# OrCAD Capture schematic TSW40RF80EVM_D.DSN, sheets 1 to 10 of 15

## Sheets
1 SHEET 01 - COVER: title: COVER; rev: D; note: TSW40RF80EVM
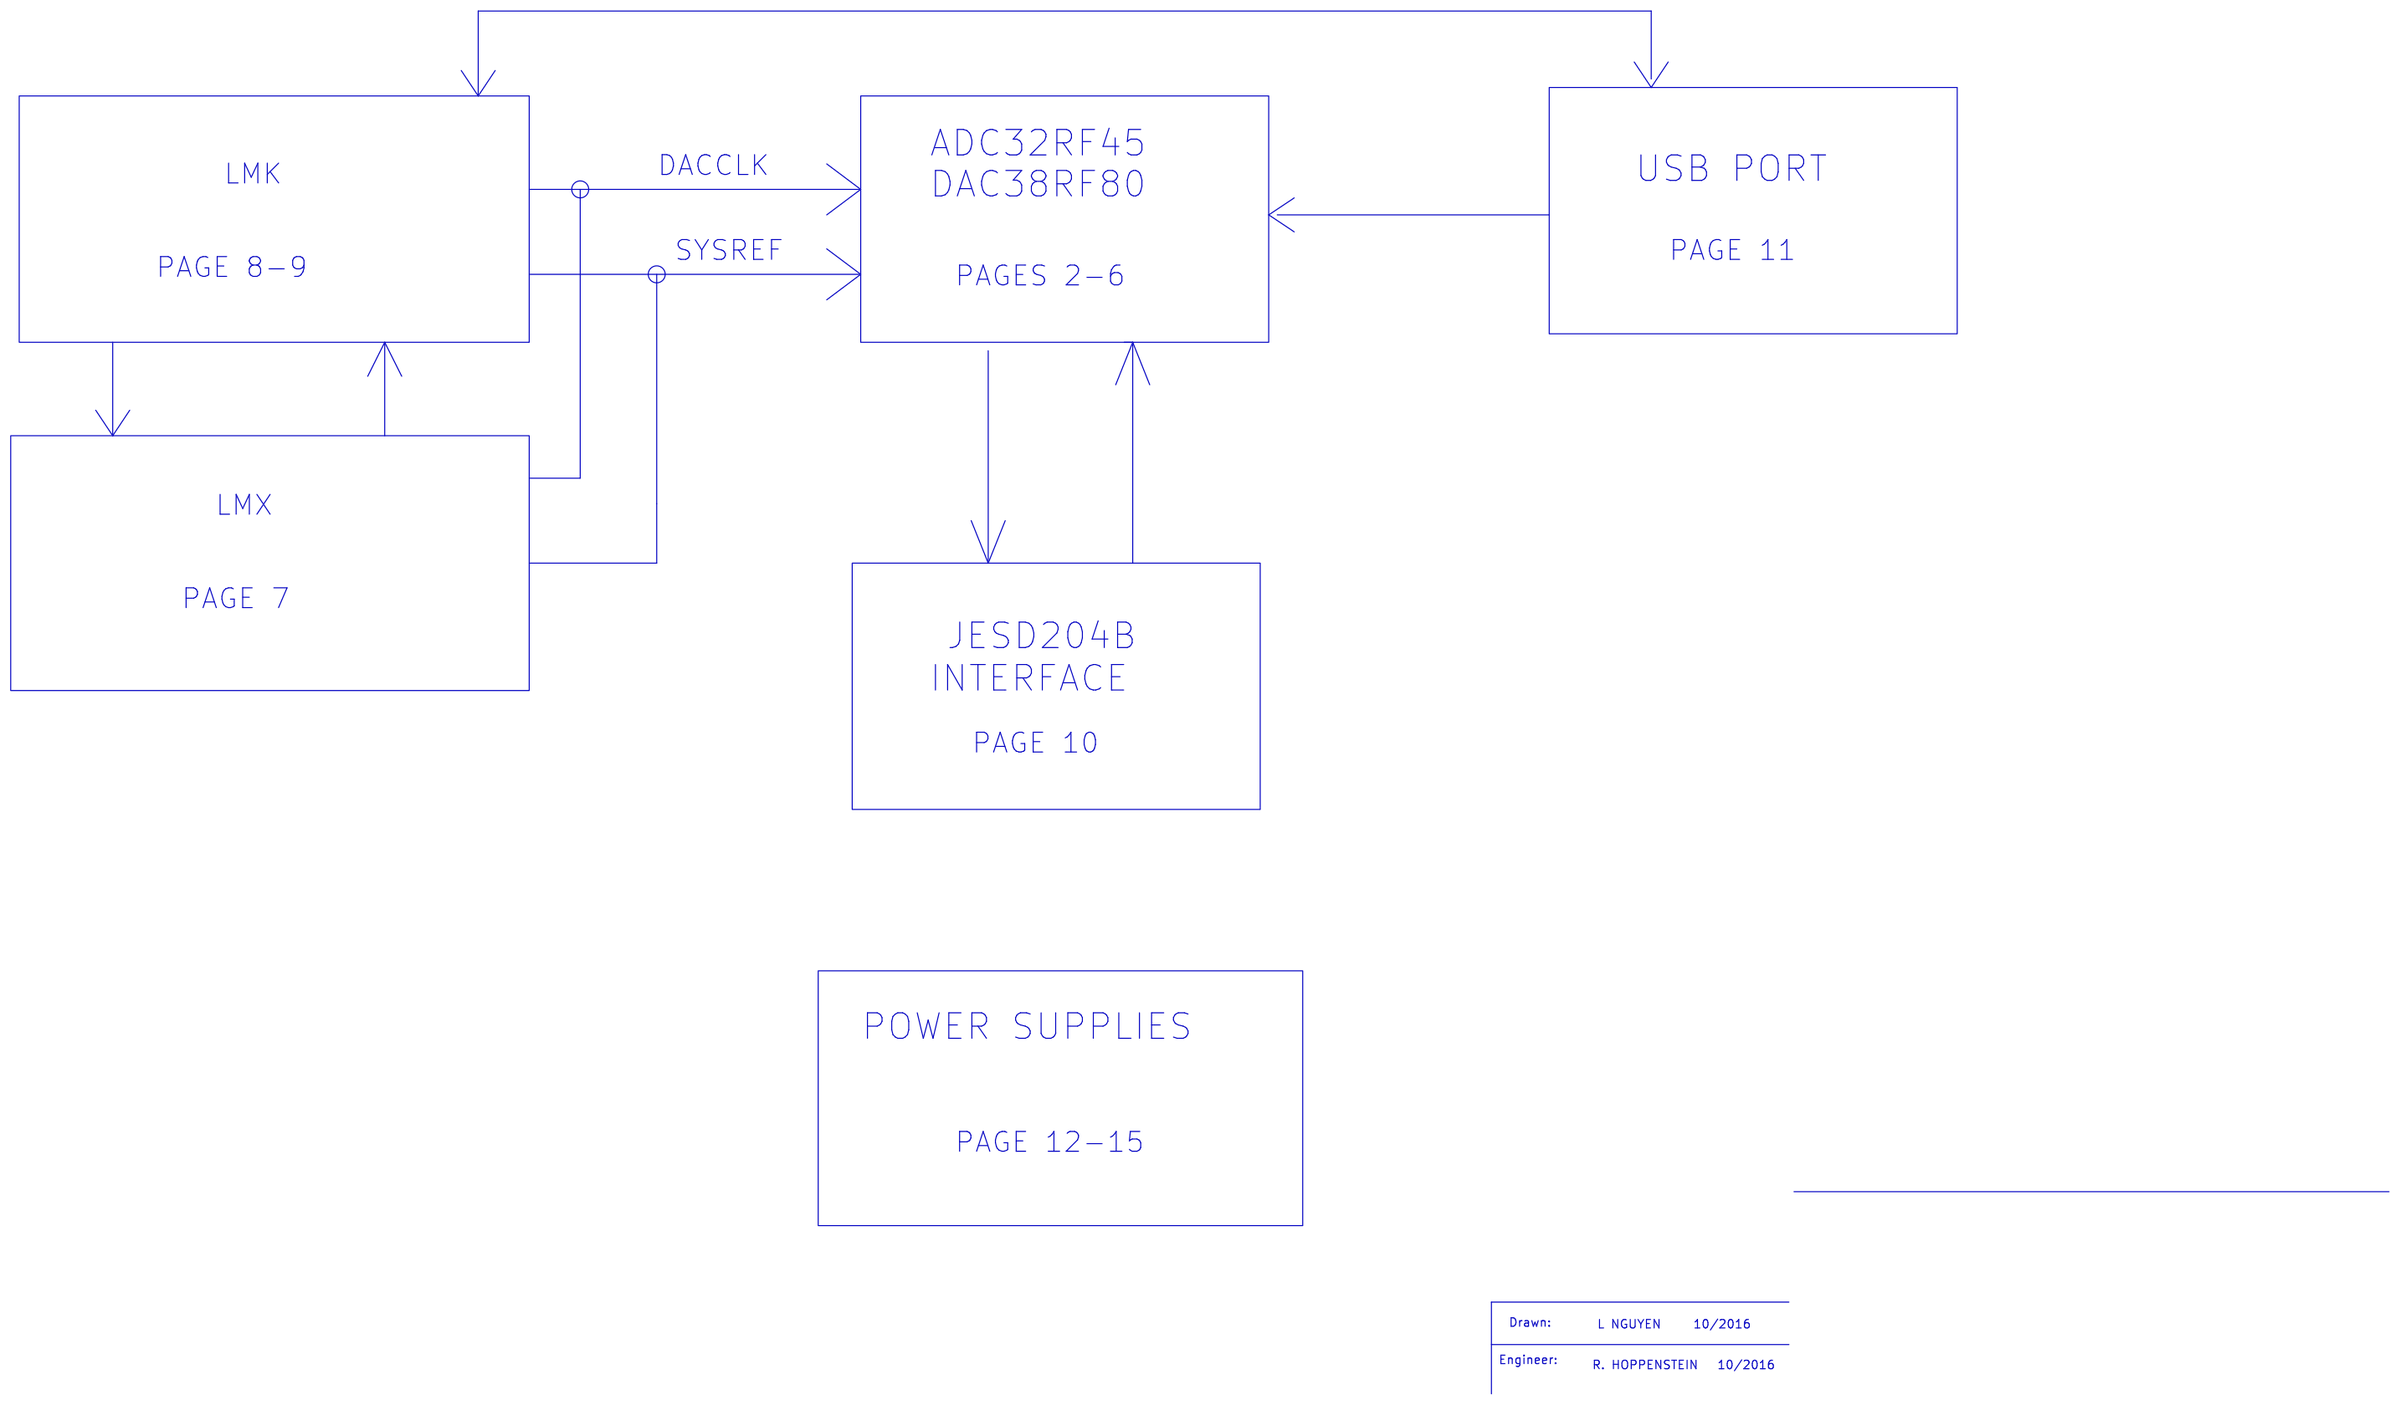
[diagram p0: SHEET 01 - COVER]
2 SHEET 02 - DAC: size B; title: DAC
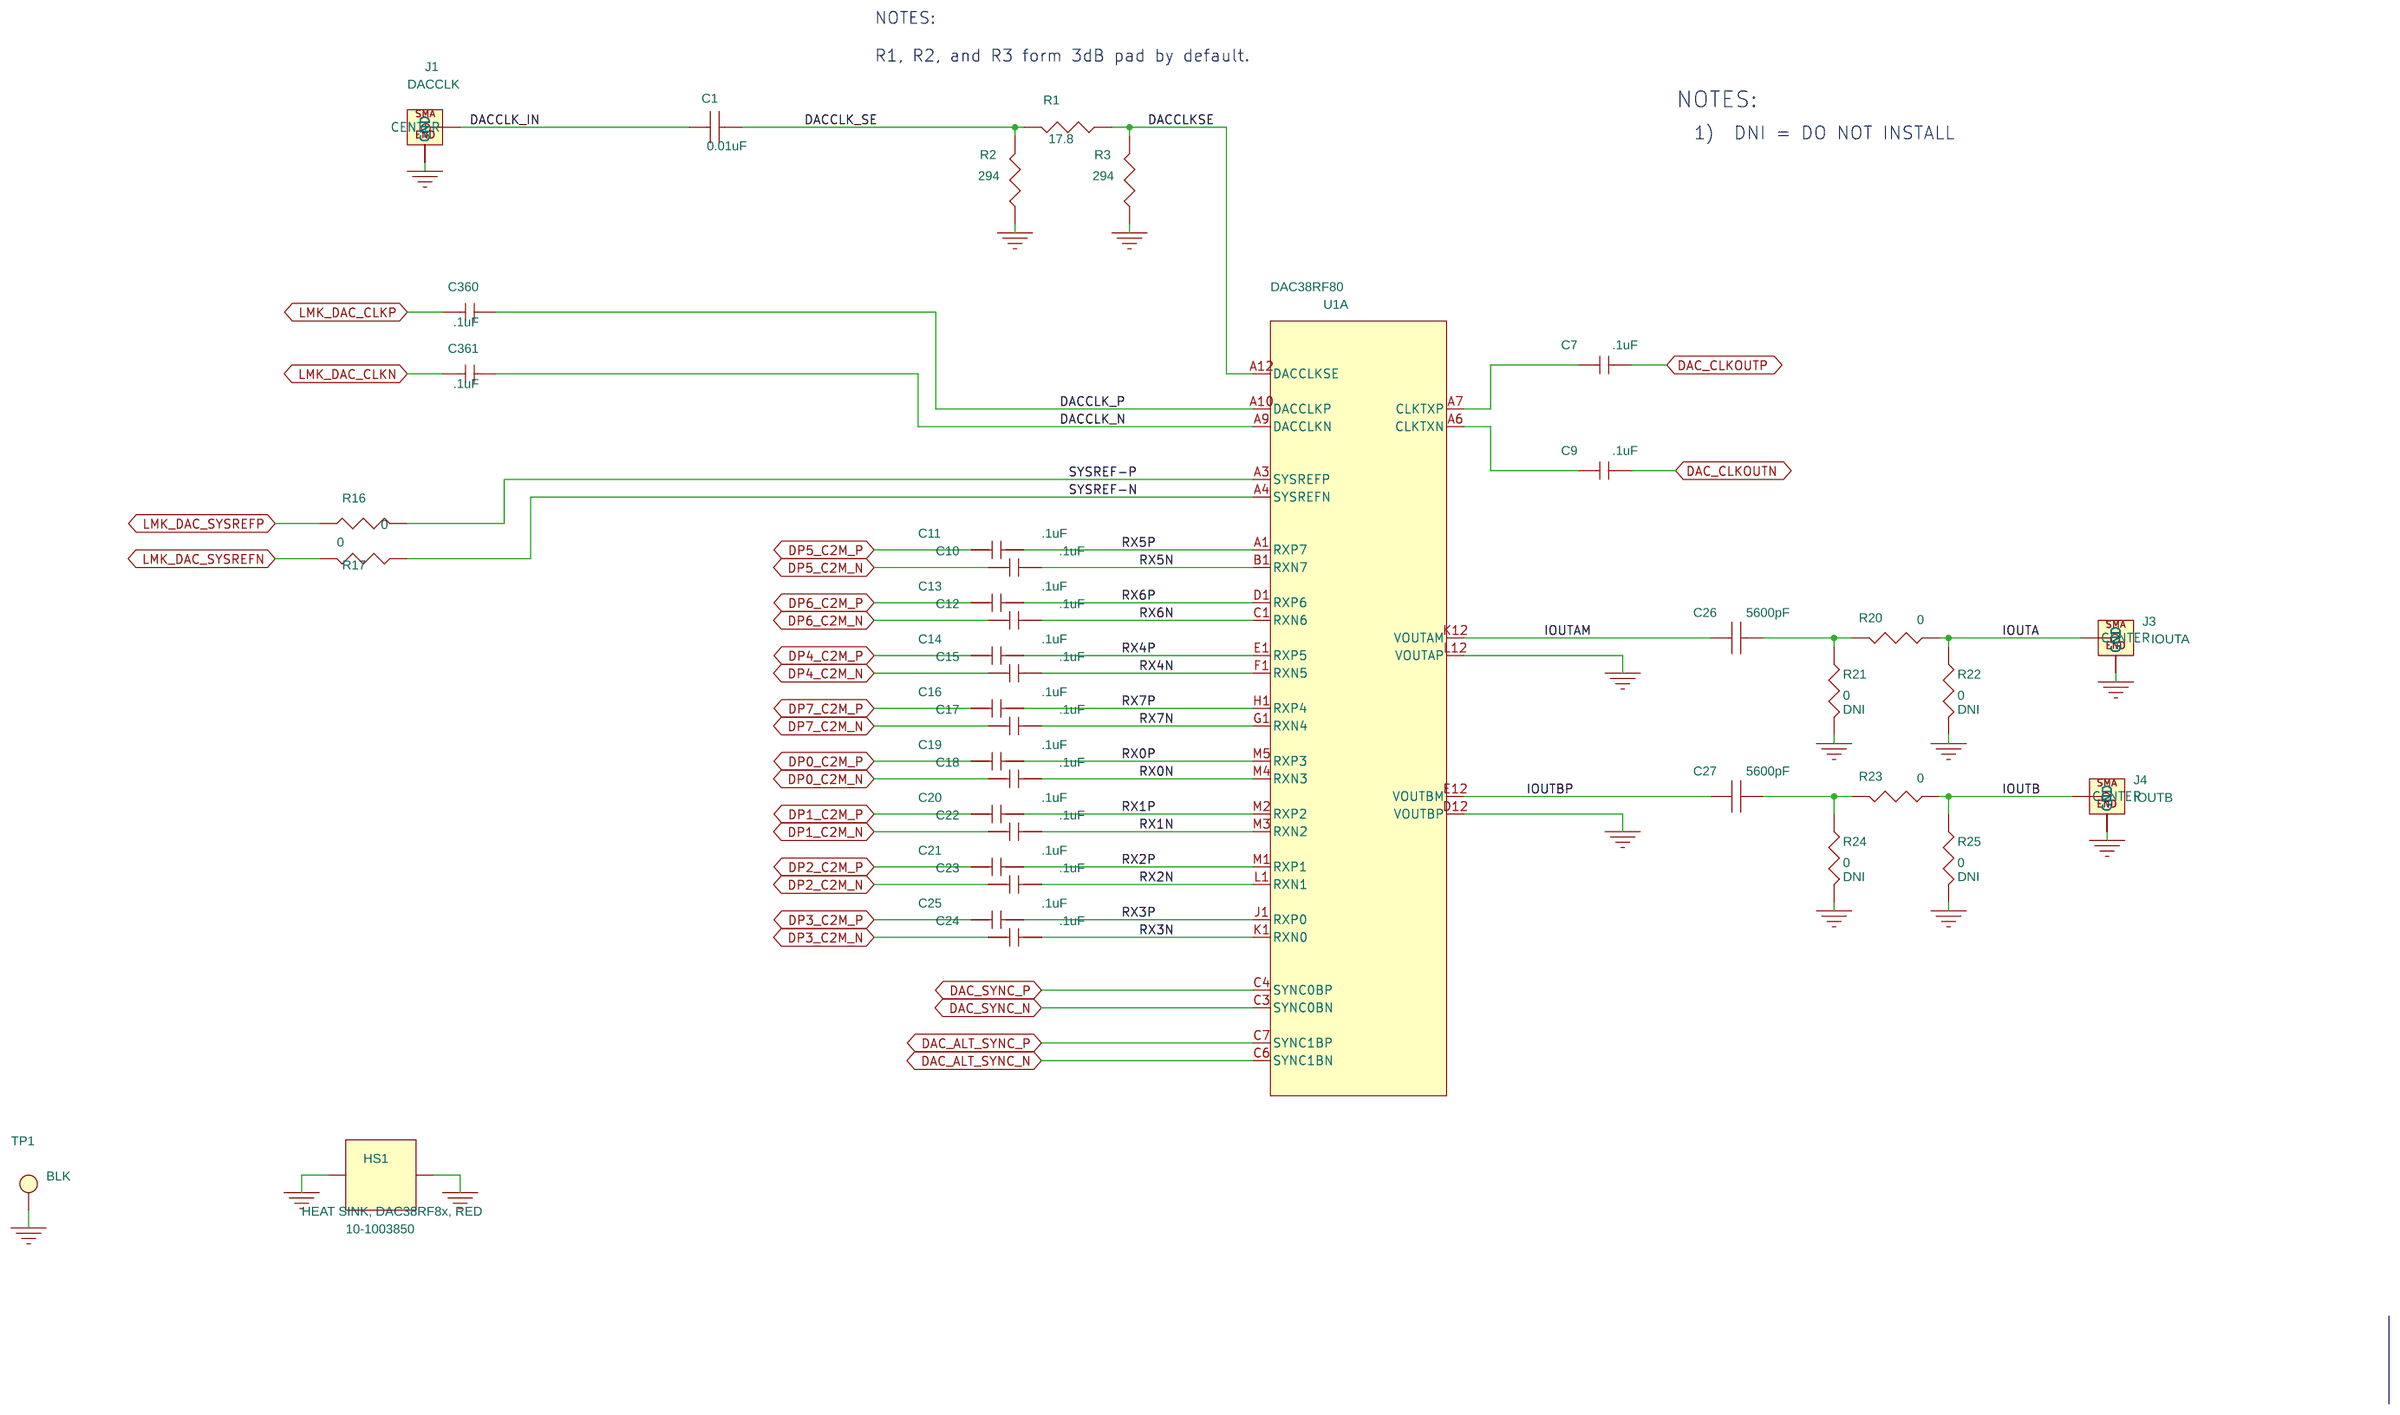
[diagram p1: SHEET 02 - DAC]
3 SHEET 03 - DAC OUTPUT: size B; title: DAC
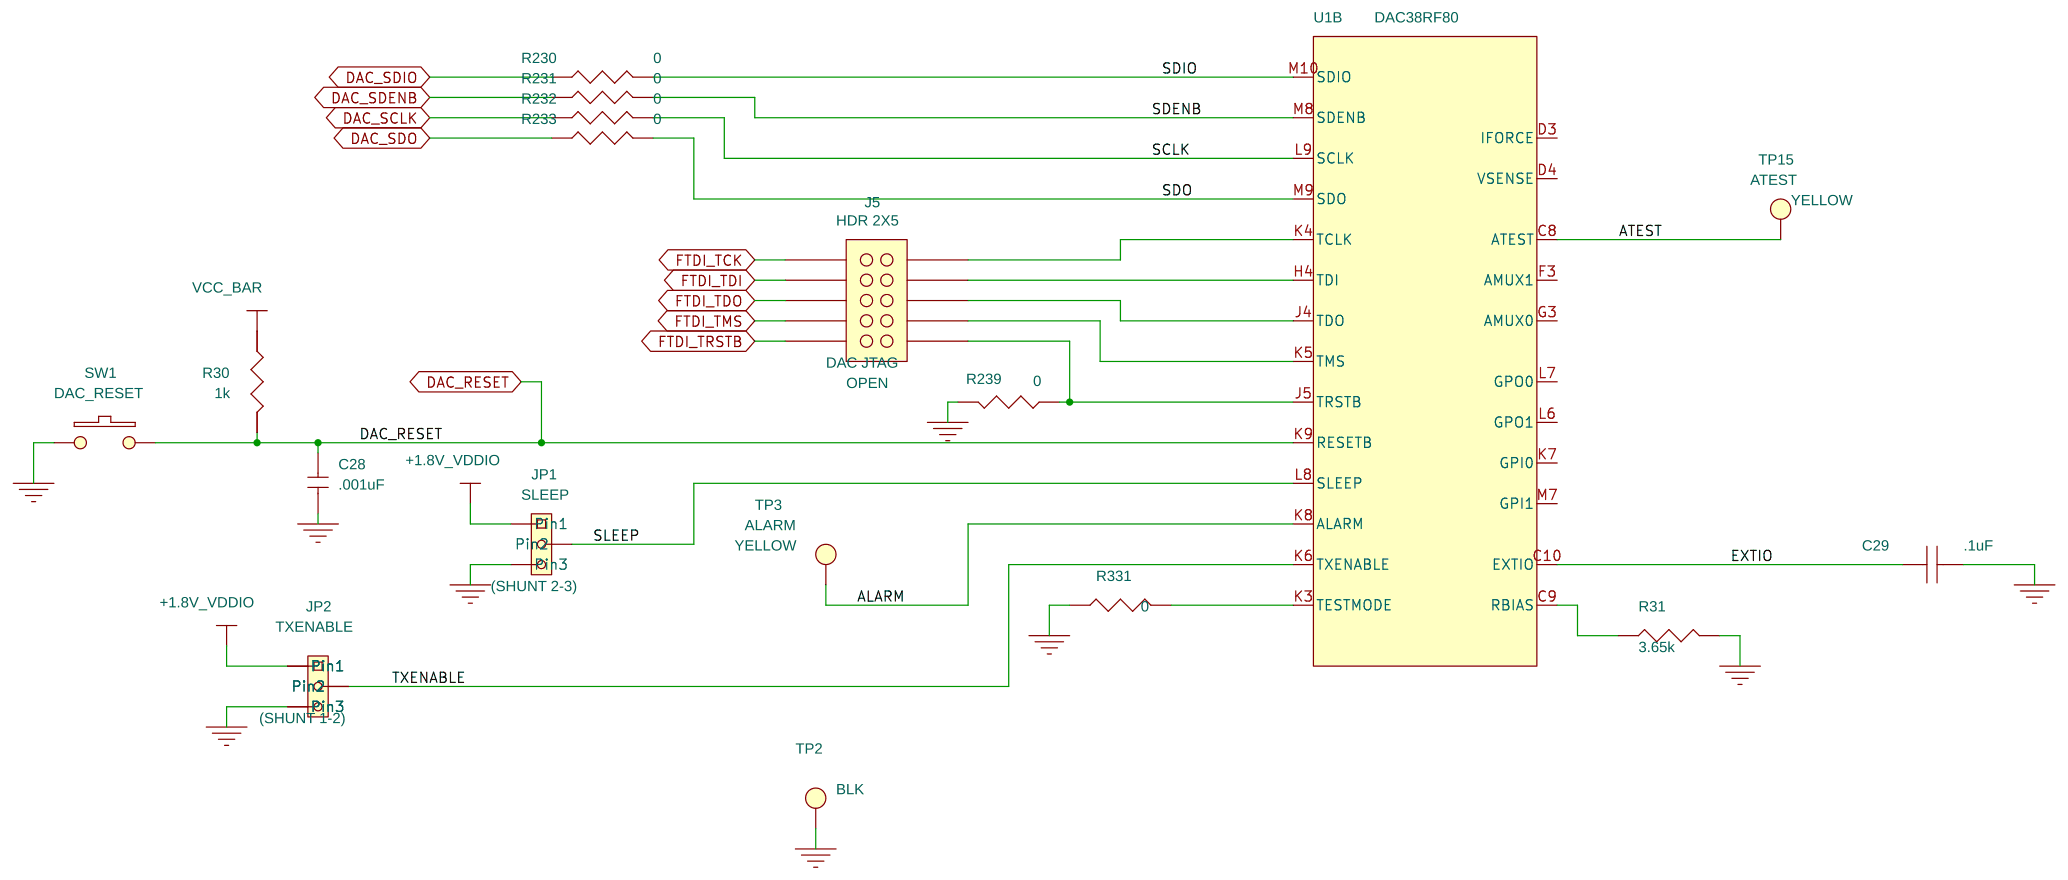
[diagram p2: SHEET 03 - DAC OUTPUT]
4 SHEET 04 - DAC POWER: size B; title: DAC POWER
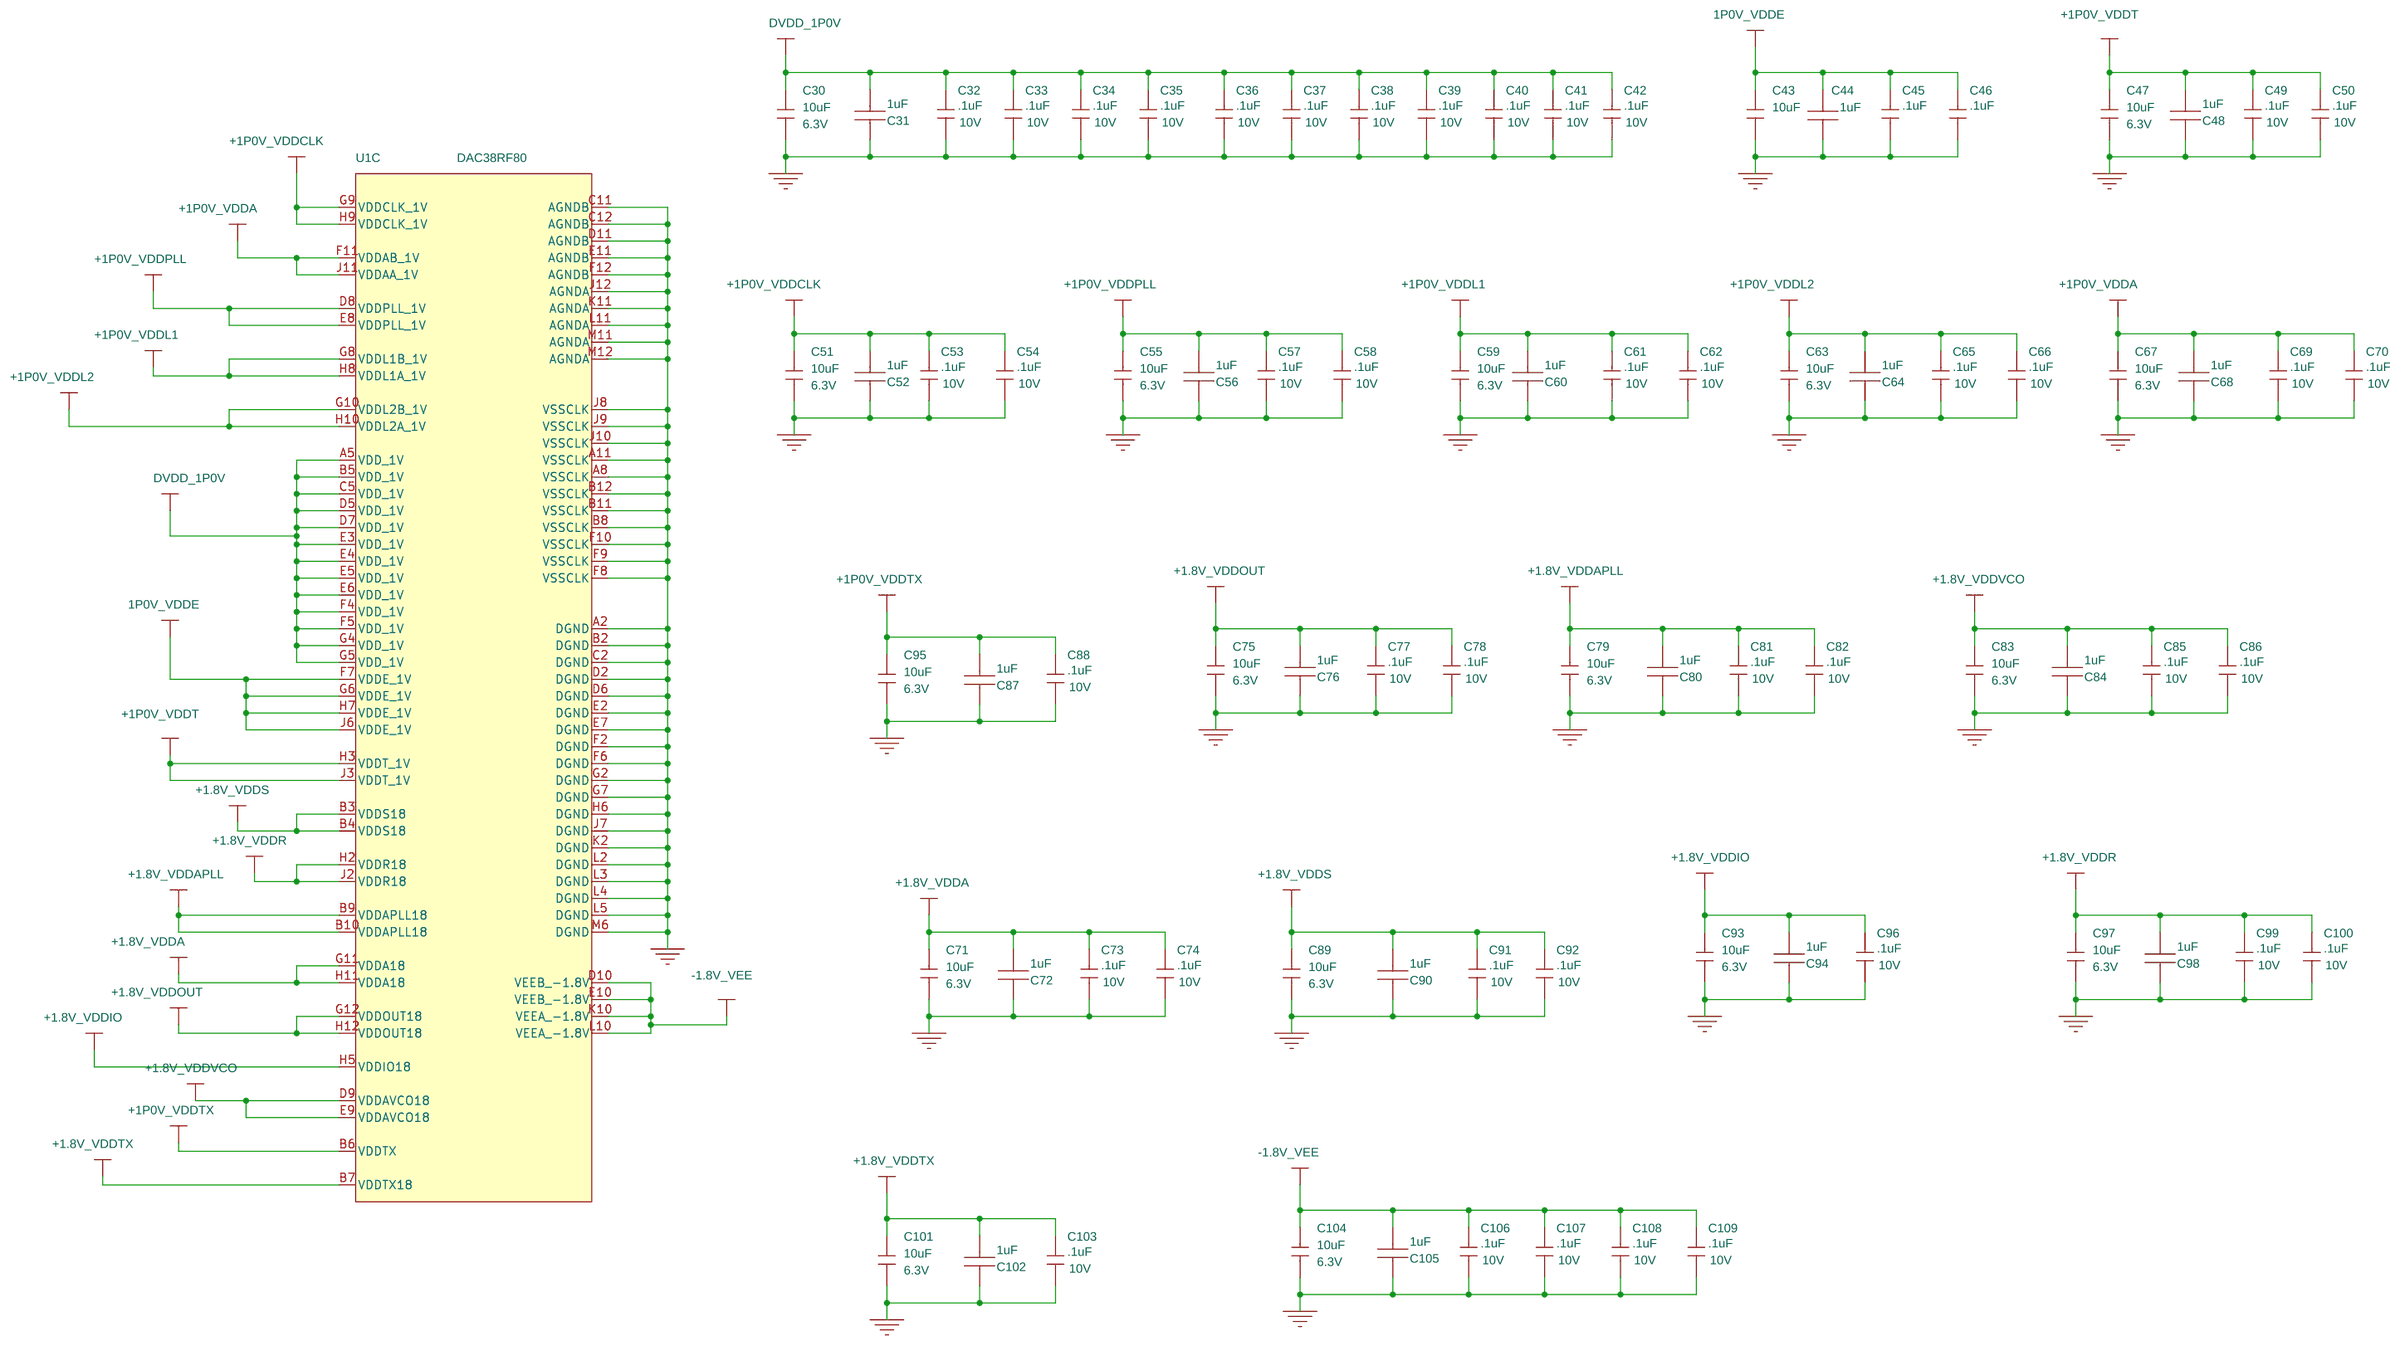
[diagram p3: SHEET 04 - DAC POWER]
5 SHEET 05 - ADC: size B; title: ADC
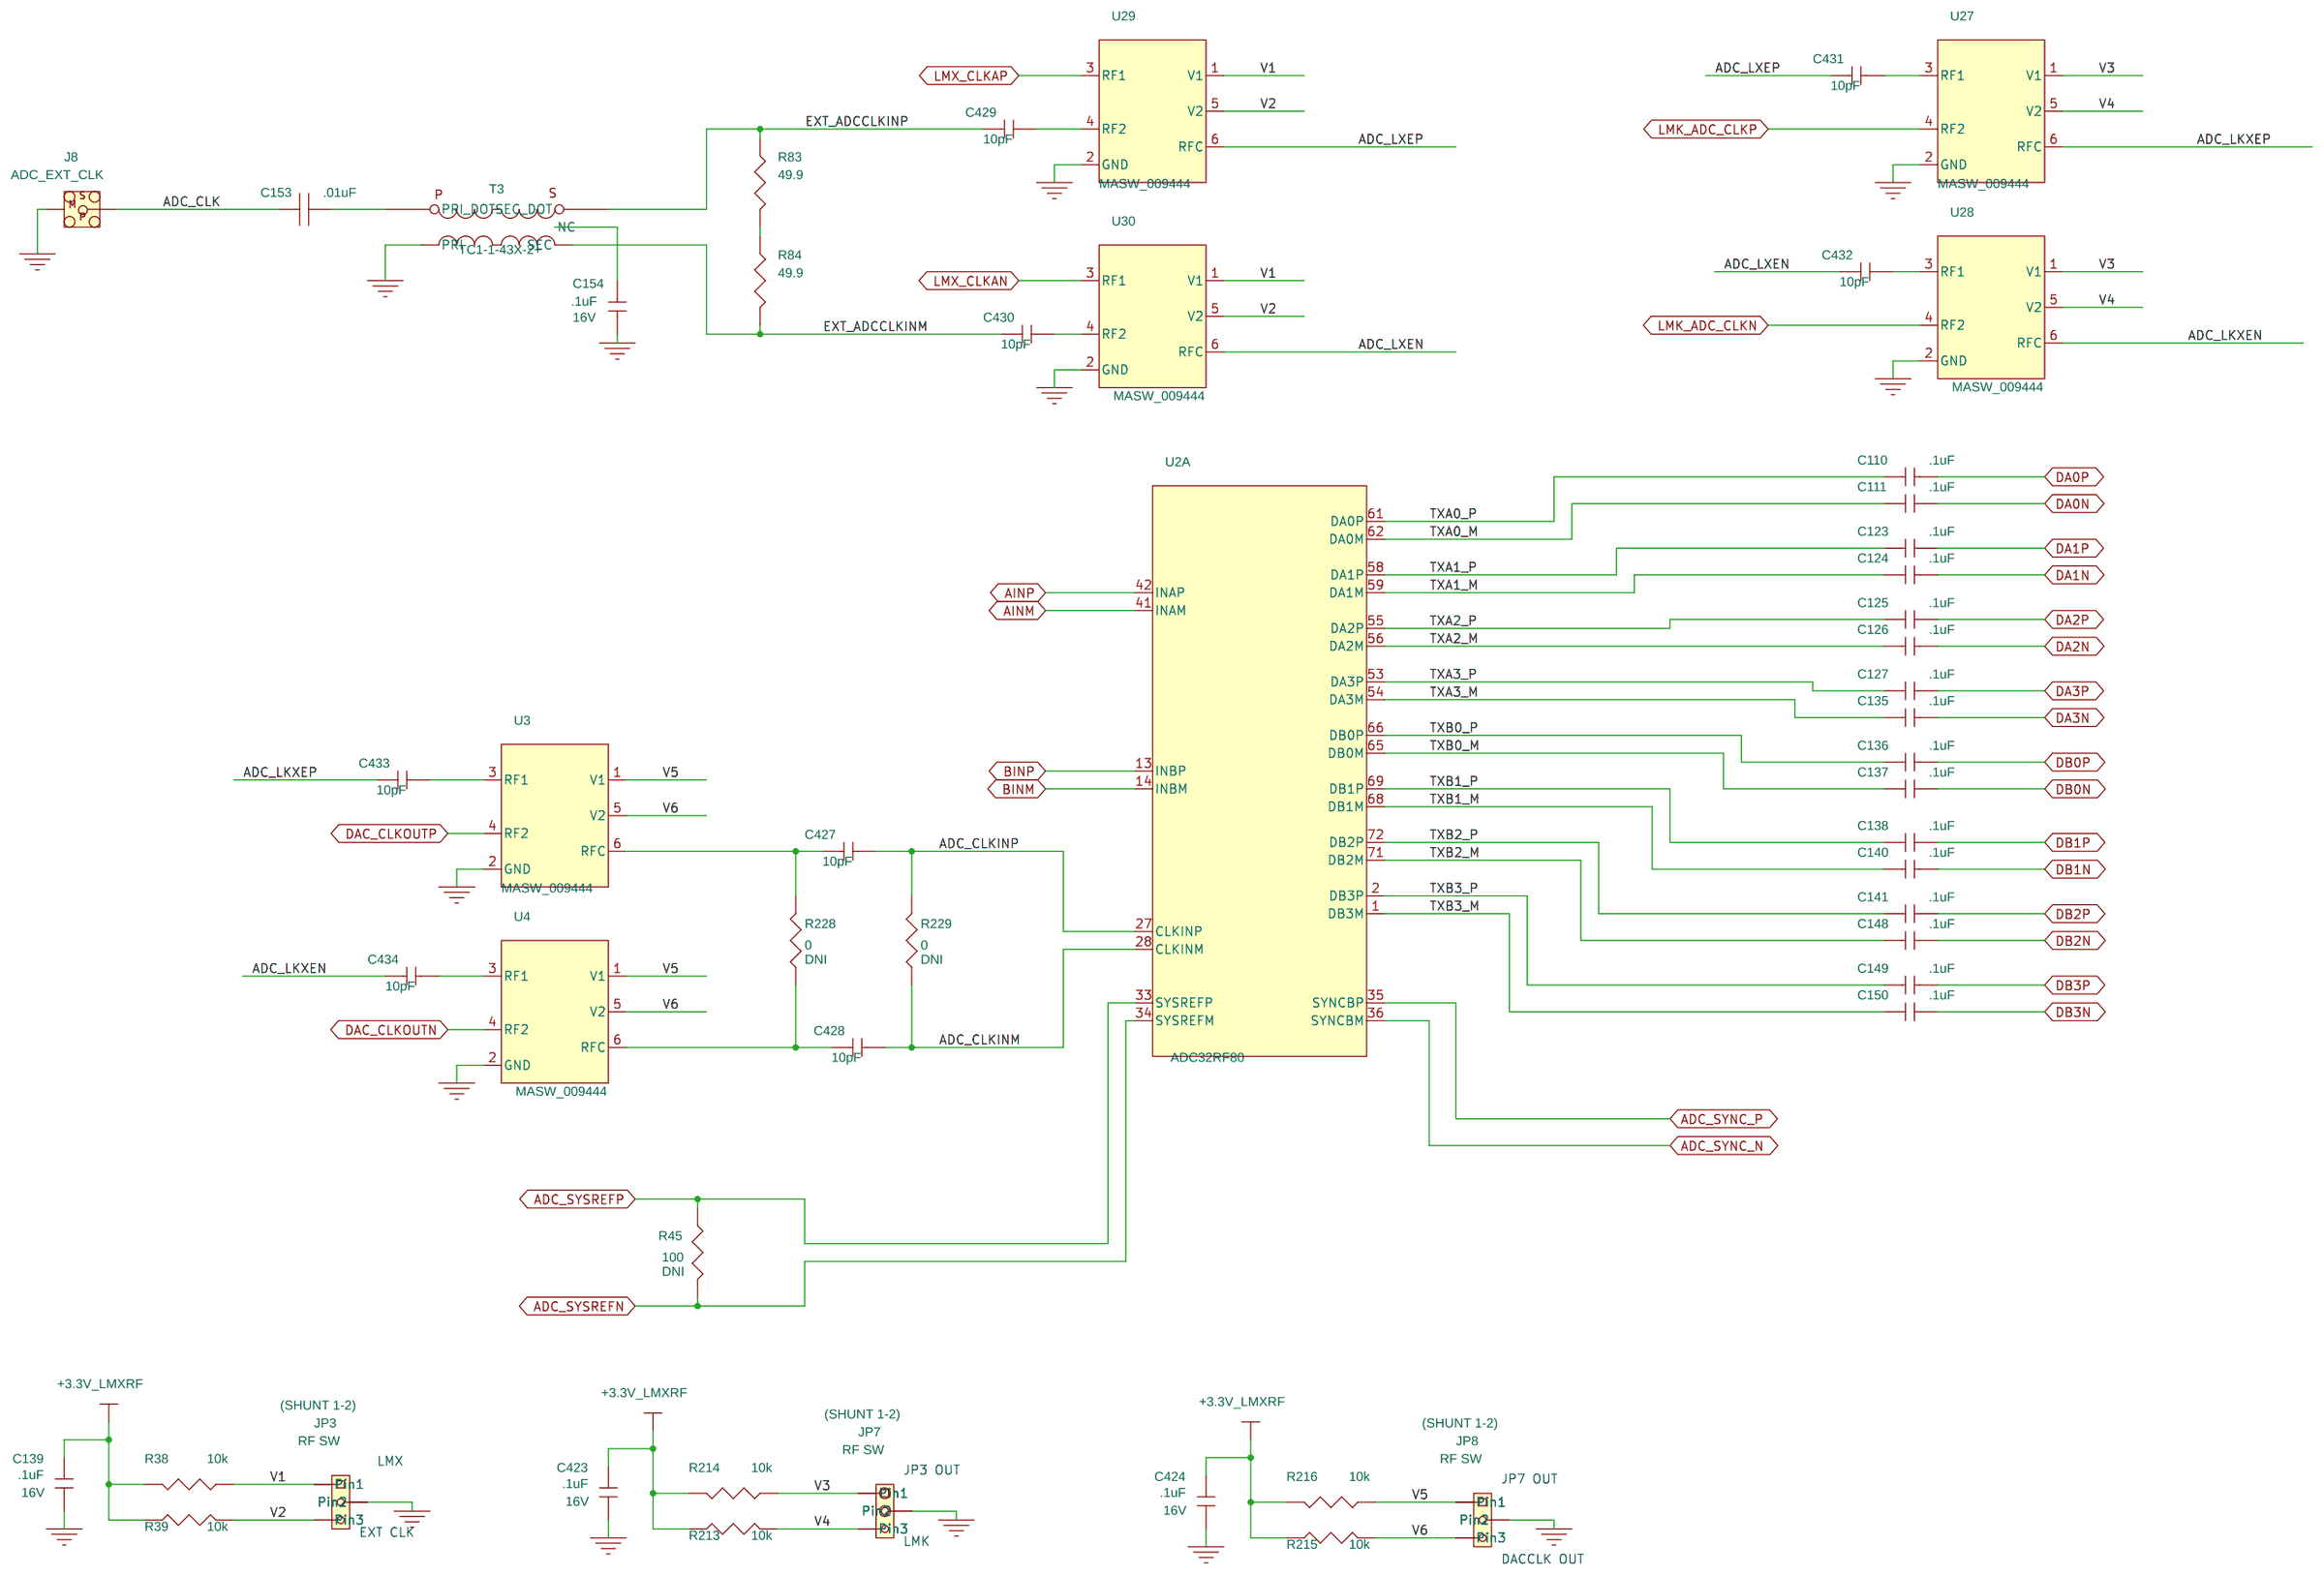
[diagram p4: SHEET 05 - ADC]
6 SHEET 06 - ADC INPUT: size B; title: ADC INPUT
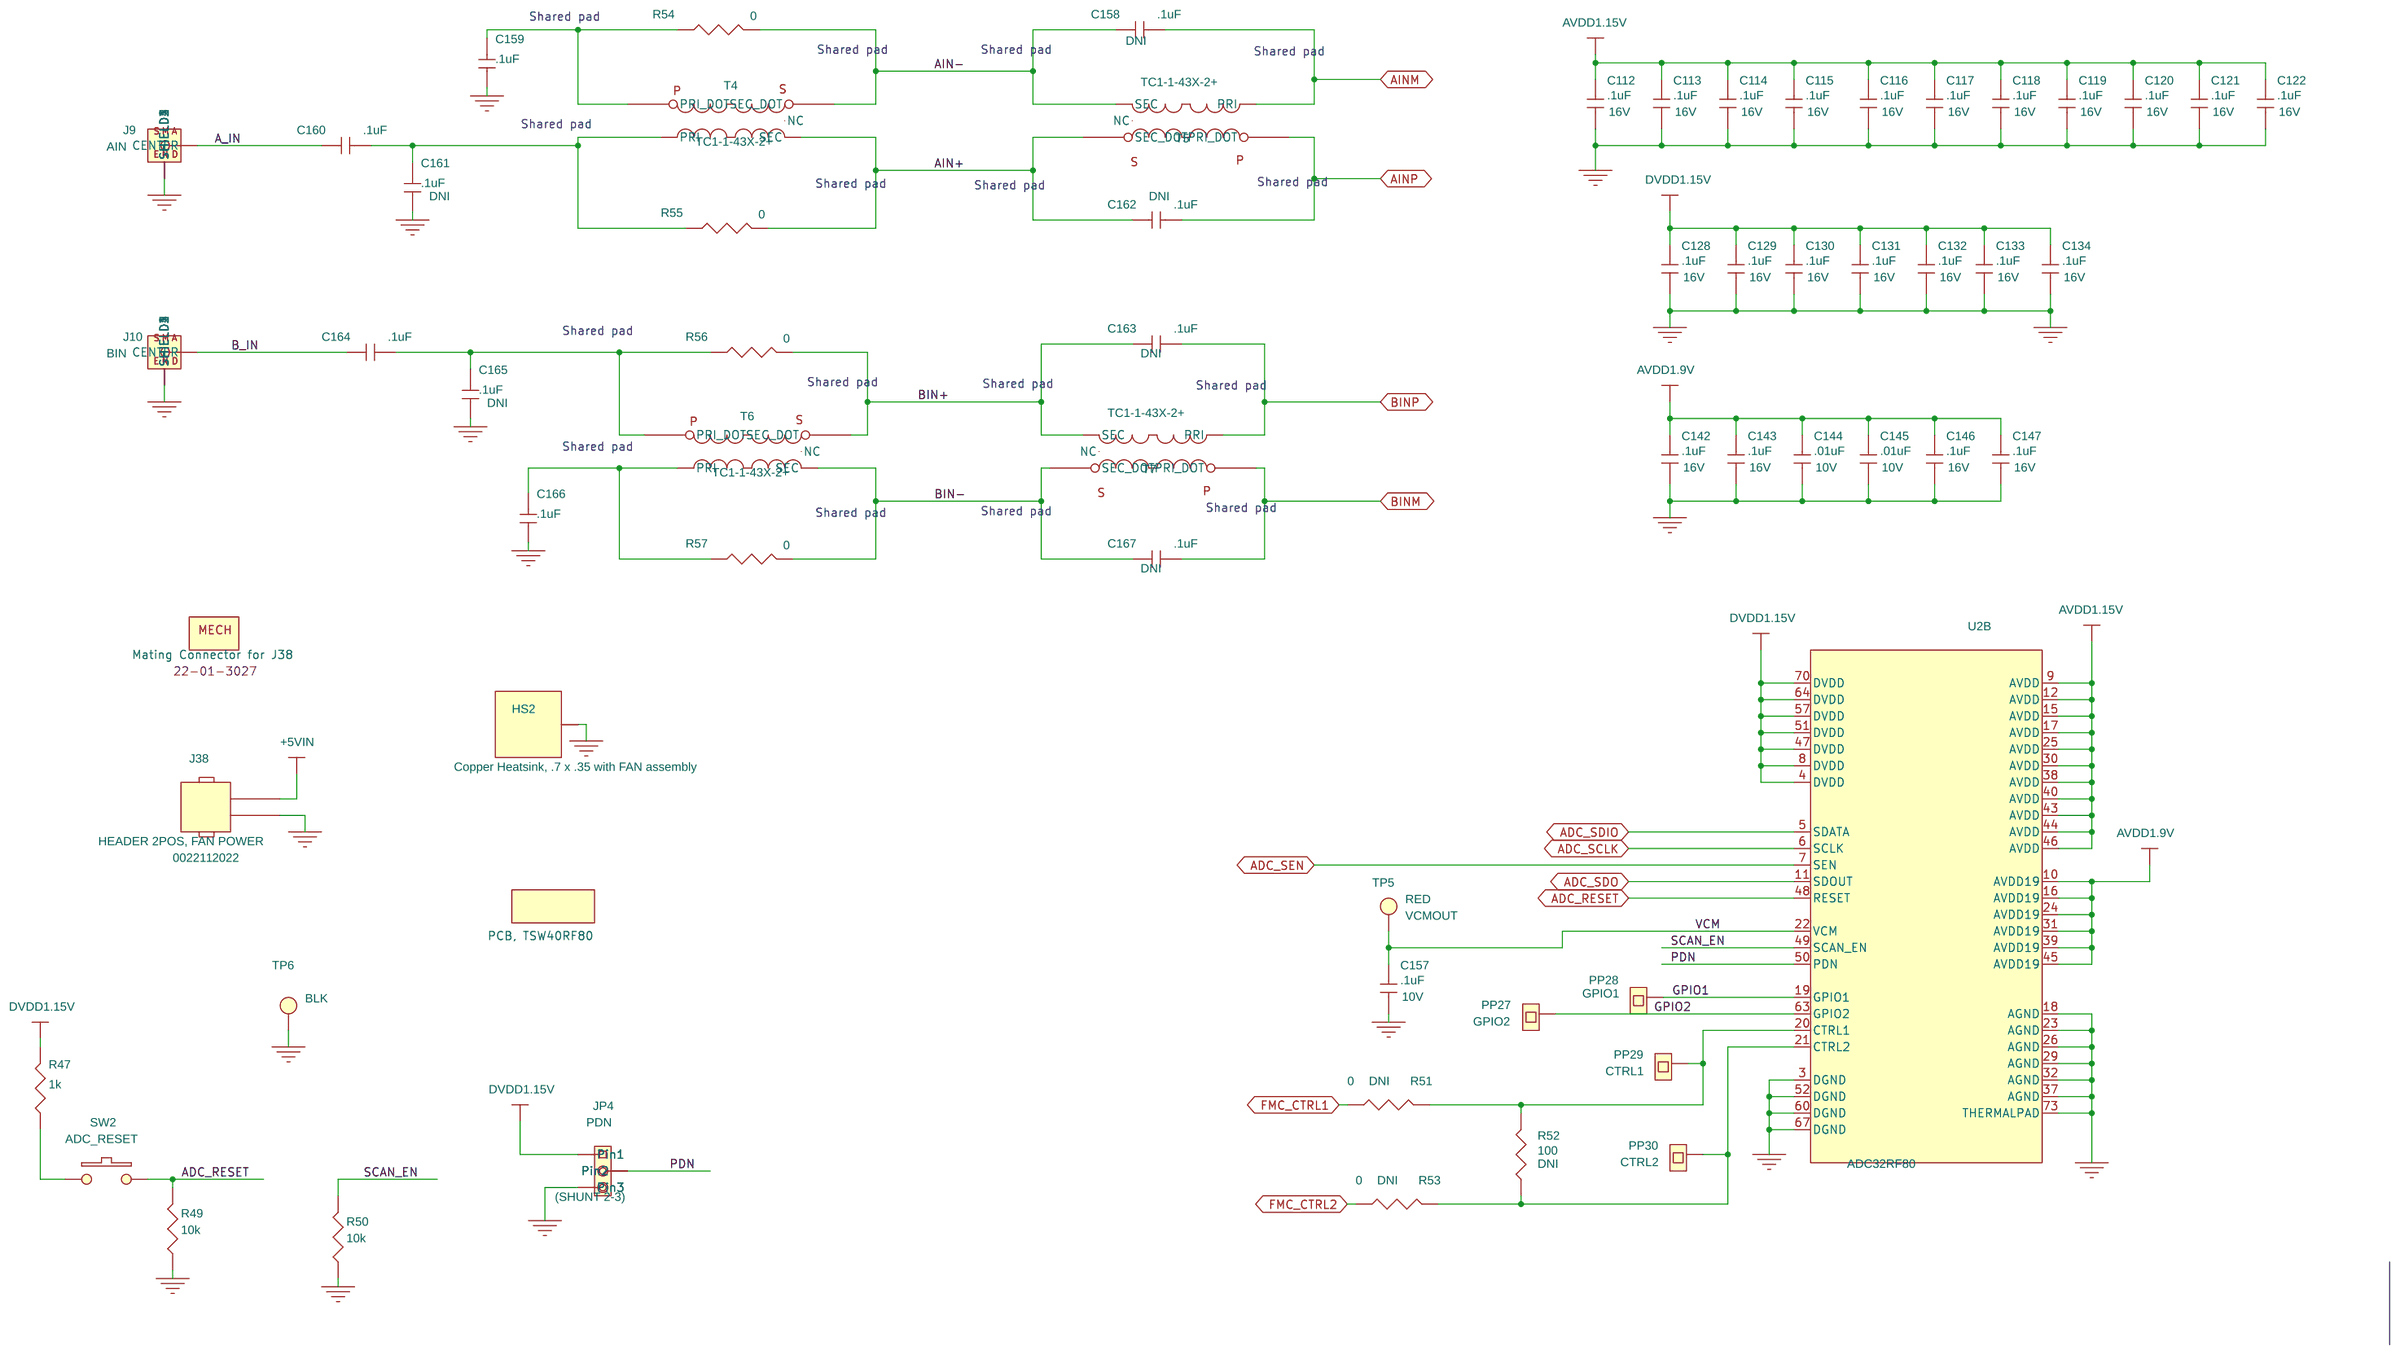
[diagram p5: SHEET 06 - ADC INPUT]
7 SHEET 07 - LMX: size B; title: LMX
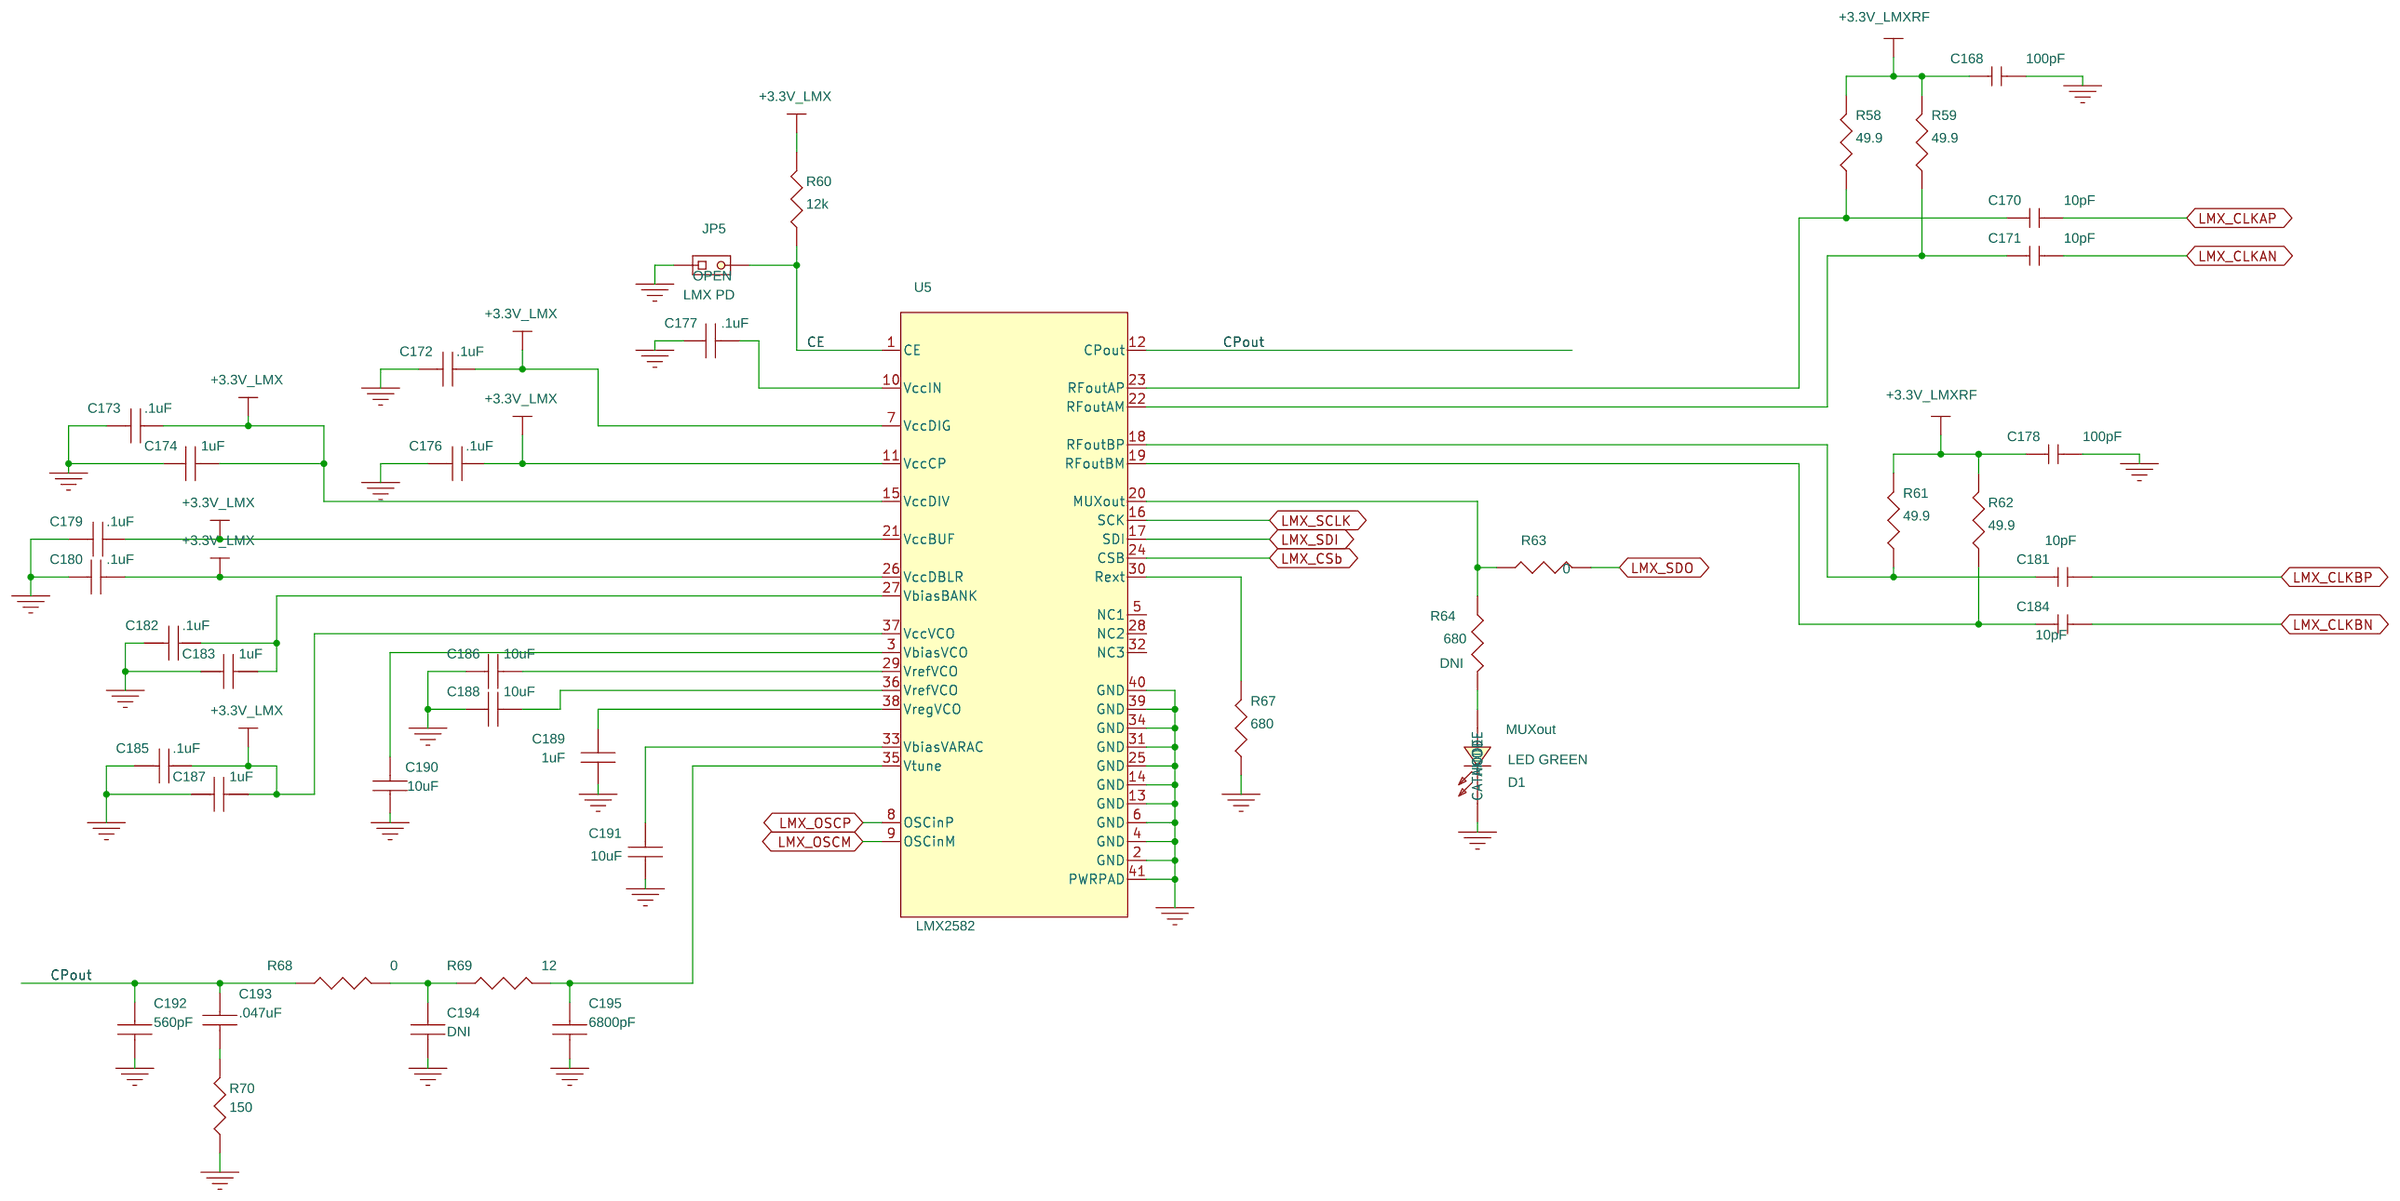
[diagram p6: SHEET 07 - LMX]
8 SHEET 08 - LMK INPUTS & OUTPUTS: size B; title: LMK
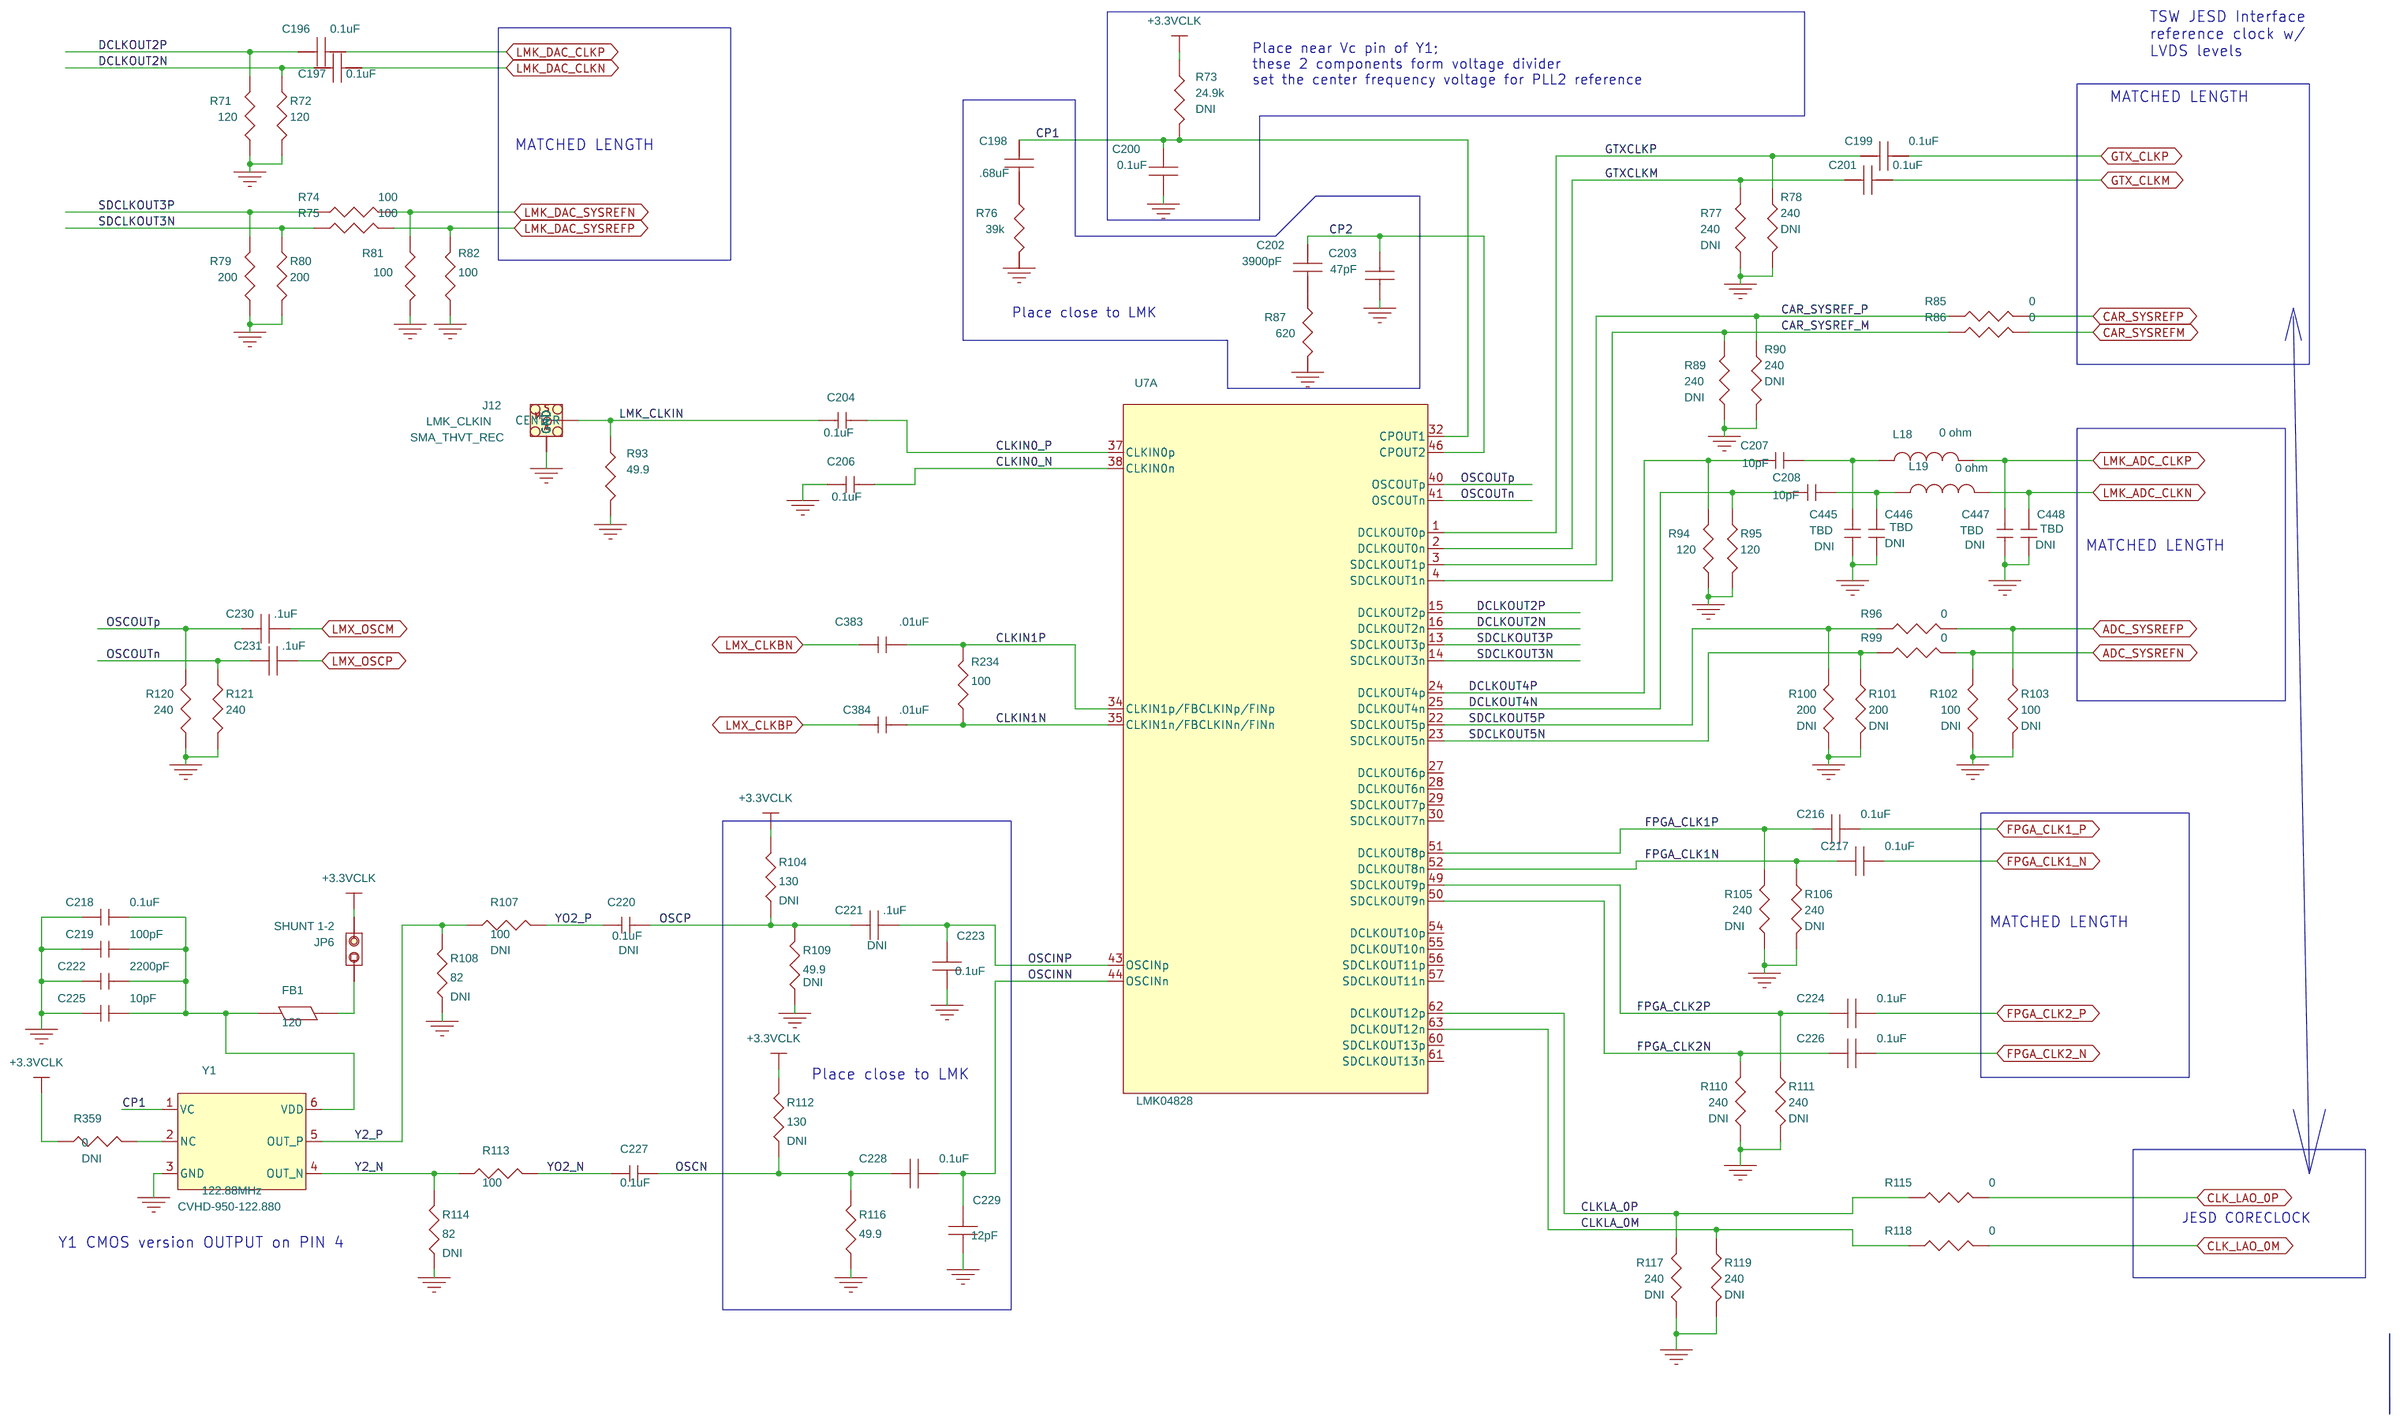
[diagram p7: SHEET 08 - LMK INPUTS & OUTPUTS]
9 SHEET 09 - LMK POWER & CONF: size B; title: LMK
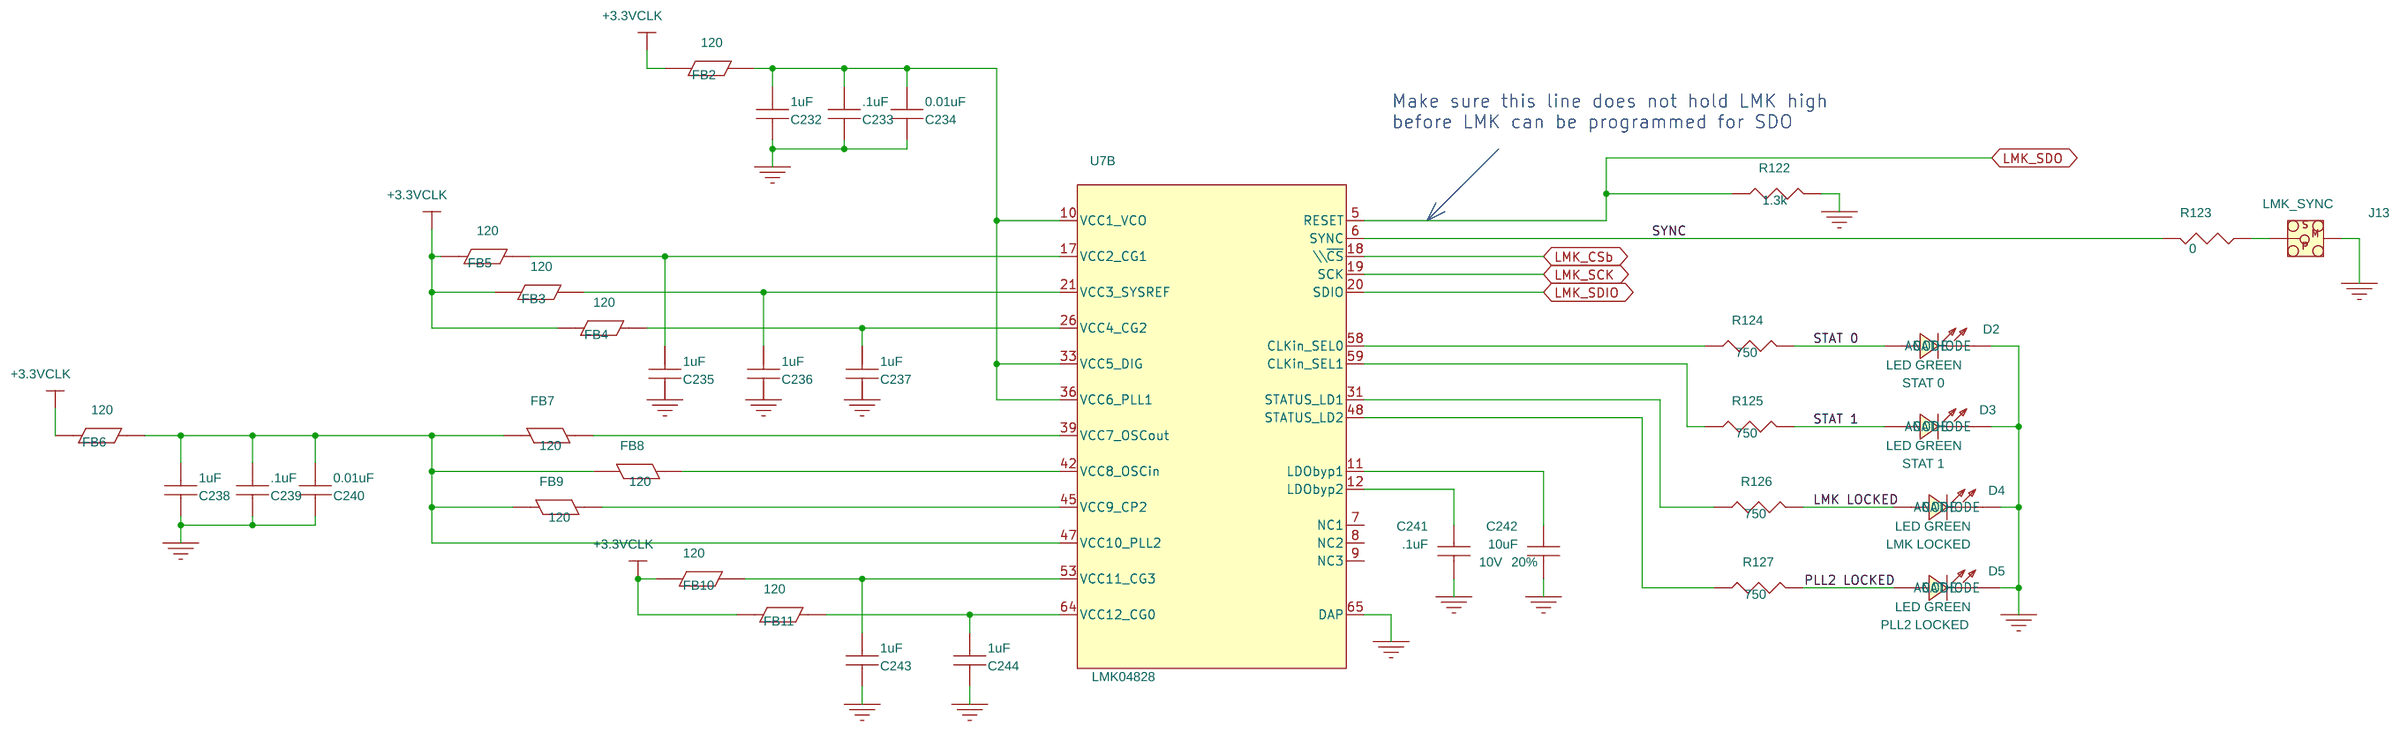
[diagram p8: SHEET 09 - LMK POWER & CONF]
10 SHEET 10 - FMC CONN: size B; title: FMC
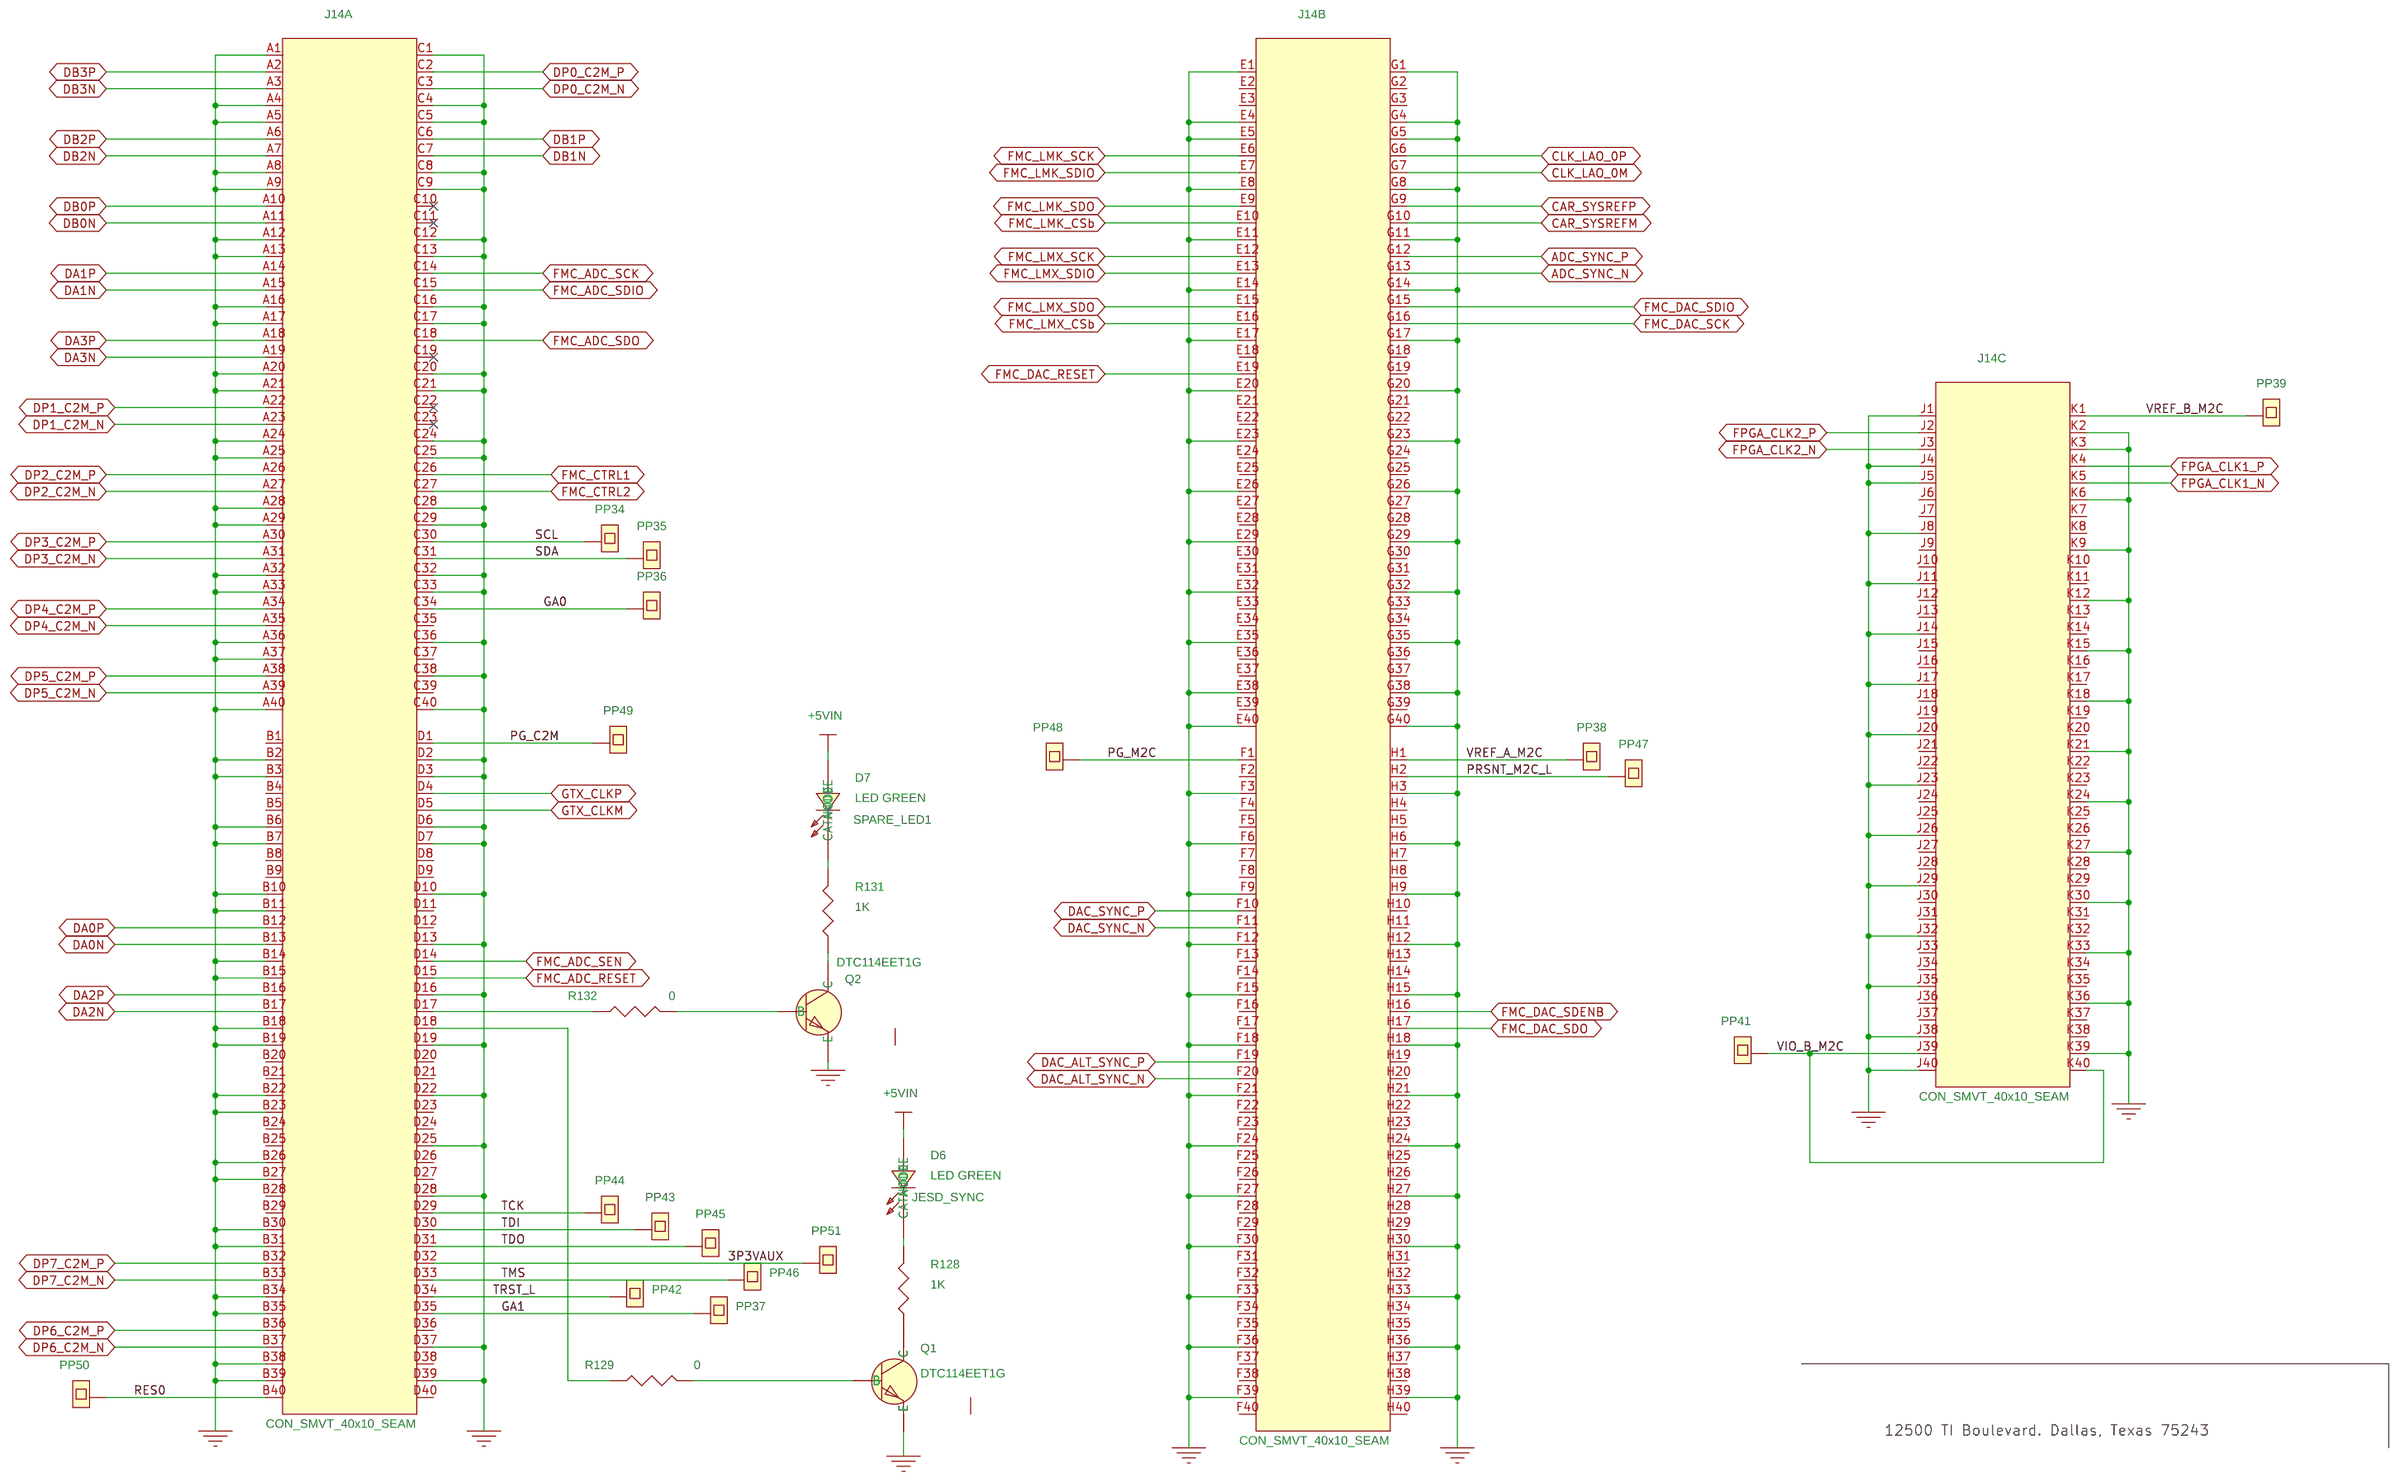
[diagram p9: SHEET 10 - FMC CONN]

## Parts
sheet SHEET 02 - DAC
C1  0.01uF  [0402]
C7  .1uF  [0201]
C9  .1uF  [0201]
C10  .1uF  [0201]
C11  .1uF  [0201]
C12  .1uF  [0201]
C13  .1uF  [0201]
C14  .1uF  [0201]
C15  .1uF  [0201]
C16  .1uF  [0201]
C17  .1uF  [0201]
C18  .1uF  [0201]
C19  .1uF  [0201]
C20  .1uF  [0201]
C21  .1uF  [0201]
C22  .1uF  [0201]
C23  .1uF  [0201]
C24  .1uF  [0201]
C25  .1uF  [0201]
C26  5600pF  [0402]
C27  5600pF  [0402]
C360  .1uF  [0201]
C361  .1uF  [0201]
HS1  HEAT SINK, DAC38RF8x, RED  [HEATSINK_SVT_10-1003850]
J1  SMA, JACK, END LAUNCH  [SMA_SMEL_DUAL_PSF-S01_250x215]
J3  SMA, JACK, END LAUNCH  [SMA_SMEL_DUAL_PSF-S01_250x215]
J4  SMA, JACK, END LAUNCH  [SMA_SMEL_DUAL_PSF-S01_250x215]
R1  17.8  [0201]
R2  294  [0201]
R3  294  [0201]
R16  0  [0201]
R17  0  [0201]
R20  0  [0402]
R21  0  [0402]
R22  0  [0402]
R23  0  [0402]
R24  0  [0402]
R25  0  [0402]
TP1  BLK  [TP_THVT_060_RND]
U1  DAC38RF80  [BGA_144_10MMx10MM_0P80MM]  (sections A,B,C)
sheet SHEET 03 - DAC OUTPUT
C28  .001uF  [0402]
C29  .1uF  [0201]
J5  HDR 2X5  [HDR_THVT_2x5_79_M]
JP1  HDR 1x3 2mm  [HDR_THVT_1x3_79_M]
JP2  HDR 1x3 2mm  [HDR_THVT_1x3_79_M]
R30  1k  [0402]
R31  3.65k  [0201]
R230  0  [0402]
R231  0  [0402]
R232  0  [0402]
R233  0  [0402]
R239  0  [0402]
R331  0  [0201]
SHN9  SHUNT, JUMPER 2mm
SW1  SWITCH, SMT, PUSHBUTTON  [SW_SMVT_SPST_EVQPJX_2]
TP2  BLK  [TP_THVT_060_RND]
TP3  YELLOW  [TP_THVT_060_RND]
TP15  YELLOW  [TP_THVT_060_RND]
sheet SHEET 04 - DAC POWER
C30  10uF  [0603]
C31  1uF  [0402]
C32  .1uF  [0201]
C33  .1uF  [0201]
C34  .1uF  [0201]
C35  .1uF  [0201]
C36  .1uF  [0201]
C37  .1uF  [0201]
C38  .1uF  [0201]
C39  .1uF  [0201]
C40  .1uF  [0201]
C41  .1uF  [0201]
C42  .1uF  [0201]
C43  10uF  [0603]
C44  1uF  [0201]
C45  .1uF  [0201]
C46  .1uF  [0201]
C47  10uF  [0603]
C48  1uF  [0402]
C49  .1uF  [0201]
C50  .1uF  [0201]
C51  10uF  [0603]
C52  1uF  [0402]
C53  .1uF  [0201]
C54  .1uF  [0201]
C55  10uF  [0603]
C56  1uF  [0402]
C57  .1uF  [0201]
C58  .1uF  [0201]
C59  10uF  [0603]
C60  1uF  [0402]
C61  .1uF  [0201]
C62  .1uF  [0201]
C63  10uF  [0603]
C64  1uF  [0402]
C65  .1uF  [0201]
C66  .1uF  [0201]
C67  10uF  [0603]
C68  1uF  [0402]
C69  .1uF  [0201]
C70  .1uF  [0201]
C71  10uF  [0603]
C72  1uF  [0402]
C73  .1uF  [0201]
C74  .1uF  [0201]
C75  10uF  [0603]
C76  1uF  [0402]
C77  .1uF  [0201]
C78  .1uF  [0201]
C79  10uF  [0603]
C80  1uF  [0402]
C81  .1uF  [0201]
C82  .1uF  [0201]
C83  10uF  [0603]
C84  1uF  [0402]
C85  .1uF  [0201]
C86  .1uF  [0201]
C87  1uF  [0402]
C88  .1uF  [0201]
C89  10uF  [0603]
C90  1uF  [0402]
C91  .1uF  [0201]
C92  .1uF  [0201]
C93  10uF  [0603]
C94  1uF  [0402]
C95  10uF  [0603]
C96  .1uF  [0201]
C97  10uF  [0603]
C98  1uF  [0402]
C99  .1uF  [0201]
C100  .1uF  [0201]
C101  10uF  [0603]
C102  1uF  [0402]
C103  .1uF  [0201]
C104  10uF  [0603]
C105  1uF  [0402]
C106  .1uF  [0201]
C107  .1uF  [0201]
C108  .1uF  [0201]
C109  .1uF  [0201]
sheet SHEET 05 - ADC
C110  .1uF  [0201]
C111  .1uF  [0201]
C123  .1uF  [0201]
C124  .1uF  [0201]
C125  .1uF  [0201]
C126  .1uF  [0201]
C127  .1uF  [0201]
C135  .1uF  [0201]
C136  .1uF  [0201]
C137  .1uF  [0201]
C138  .1uF  [0201]
C139  .1uF  [0201]
C140  .1uF  [0201]
C141  .1uF  [0201]
C148  .1uF  [0201]
C149  .1uF  [0201]
C150  .1uF  [0201]
C153  .01uF  [0402]
C154  .1uF  [0402]
C423  .1uF  [0201]
C424  .1uF  [0201]
C427  10pF  [0201]
C428  10pF  [0201]
C429  10pF  [0201]
C430  10pF  [0201]
C431  10pF  [0201]
C432  10pF  [0201]
C433  10pF  [0201]
C434  10pF  [0201]
J8  SMP CONN  [smp_b120]
JP3  HDR 1x3 2mm  [HDR_THVT_1x3_79_M]
JP7  HDR 1x3 2mm  [HDR_THVT_1x3_79_M]
JP8  HDR 1x3 2mm  [HDR_THVT_1x3_79_M]
R38  10k  [0402]
R39  10k  [0402]
R45  100  [0201]
R83  49.9  [0402]
R84  49.9  [0402]
R213  10k  [0402]
R214  10k  [0402]
R215  10k  [0402]
R216  10k  [0402]
R228  0  [0201]
R229  0  [0201]
SHN12  SHUNT, JUMPER 2mm
SHN13  SHUNT, JUMPER 2mm
SHN14  SHUNT, JUMPER 2mm
T3  TC1-1-43X-2+  [TFMR_5_150X150_50]
U2  ADC32RF80  [QFN_72_10MMX10MM_0P50MM_PWRPAD]  (sections A,B)
U3  MASW_009444  [PDFN_6_p35mm]
U4  MASW_009444  [PDFN_6_p35mm]
U27  MASW_009444  [PDFN_6_p35mm]
U28  MASW_009444  [PDFN_6_p35mm]
U29  MASW_009444  [PDFN_6_p35mm]
U30  MASW_009444  [PDFN_6_p35mm]
sheet SHEET 06 - ADC INPUT
C112  .1uF  [0201]
C113  .1uF  [0201]
C114  .1uF  [0201]
C115  .1uF  [0201]
C116  .1uF  [0201]
C117  .1uF  [0201]
C118  .1uF  [0201]
C119  .1uF  [0201]
C120  .1uF  [0201]
C121  .1uF  [0201]
C122  .1uF  [0201]
C128  .1uF  [0201]
C129  .1uF  [0201]
C130  .1uF  [0201]
C131  .1uF  [0201]
C132  .1uF  [0201]
C133  .1uF  [0201]
C134  .1uF  [0201]
C142  .1uF  [0201]
C143  .1uF  [0201]
C144  .01uF  [0201]
C145  .01uF  [0201]
C146  .1uF  [0201]
C147  .1uF  [0201]
C157  .1uF  [0201]
C158  .1uF  [0603]
C159  .1uF  [0402]
C160  .1uF  [0402]
C161  .1uF  [0402]
C162  .1uF  [0603]
C163  .1uF  [0603]
C164  .1uF  [0402]
C165  .1uF  [0402]
C166  .1uF  [0402]
C167  .1uF  [0603]
CONN HOUS 2POS .100  Mating Connector for J38
HS2  Copper Heatsink, .7 x .35 with FAN assembly  [HEATSINK_350X700]
J9  SMA, JACK, END LAUNCH  [SMA_SMEL_DUAL_PSF-S01_250x215]
J10  SMA, JACK, END LAUNCH  [SMA_SMEL_DUAL_PSF-S01_250x215]
J38  HEADER 2POS, FAN POWER  [hdr_thvt_1x2_100_m]
JP4  HDR 1x3 2mm  [HDR_THVT_1x3_79_M]
PP27  PROBE POINT  [PROBE_POINT_22PAD]
PP28  PROBE POINT  [PROBE_POINT_22PAD]
PP29  PROBE POINT  [PROBE_POINT_22PAD]
PP30  PROBE POINT  [PROBE_POINT_22PAD]
R47  1k  [0201]
R49  10k  [0201]
R50  10k  [0201]
R51  0  [0201]
R52  100  [0201]
R53  0  [0201]
R54  0  [0603]
R55  0  [0603]
R56  0  [0603]
R57  0  [0603]
SHN11  SHUNT, JUMPER 2mm
SW2  SWITCH, SMT, PUSHBUTTON  [SW_SMVT_SPST_EVQPJX_2]
T4  TC1-1-43X-2+  [TFMR_5_150X150_50]
T5  TC1-1-43X-2+  [TFMR_5_150X150_50]
T6  TC1-1-43X-2+  [TFMR_5_150X150_50]
T7  TC1-1-43X-2+  [TFMR_5_150X150_50]
TP5  RED  [TP_THVT_060_RND]
TP6  BLK  [TP_THVT_060_RND]
Z_BOARD1  PCB, TSW40RF80
sheet SHEET 07 - LMX
C168  100pF  [0201]
C170  10pF  [0201]
C171  10pF  [0201]
C172  .1uF  [0201]
C173  .1uF  [0201]
C174  1uF  [0201]
C176  .1uF  [0201]
C177  .1uF  [0201]
C178  100pF  [0201]
C179  .1uF  [0201]
C180  .1uF  [0201]
C181  10pF  [0201]
C182  .1uF  [0201]
C183  1uF  [0201]
C184  10pF  [0201]
C185  .1uF  [0201]
C186  10uF  [0402]
C187  1uF  [0201]
C188  10uF  [0402]
C189  1uF  [0201]
C190  10uF  [0402]
C191  10uF  [0402]
C192  560pF  [0201]
C193  .047uF  [0201]
C194  6800pF  [0201]
C195  6800pF  [0201]
D1  LED GREEN  [LED_0603]
JP5  HDR 1x2 2mm  [HDR_THVT_1x2_79_M]
R58  49.9  [0201]
R59  49.9  [0201]
R60  12k  [0402]
R61  49.9  [0201]
R62  49.9  [0201]
R63  0  [0201]
R64  680  [0201]
R67  680  [0201]
R68  0  [0201]
R69  12  [0201]
R70  150  [0201]
U5  LMX2582  [qfn40_RTA_RTB_RHA]
sheet SHEET 08 - LMK INPUTS & OUTPUTS
C196  0.1uF  [0201]
C197  0.1uF  [0201]
C198  .68uF  [0402]
C199  0.1uF  [0201]
C200  0.1uF  [0201]
C201  0.1uF  [0201]
C202  3900pF  [0201]
C203  47pF  [0201]
C204  0.1uF  [0201]
C206  0.1uF  [0201]
C207  10pF  [0201]
C208  10pF  [0201]
C216  0.1uF  [0201]
C217  0.1uF  [0201]
C218  0.1uF  [0201]
C219  100pF  [0201]
C220  0.1uF  [0201]
C221  .1uF  [0201]
C222  2200pF  [0201]
C223  0.1uF  [0201]
C224  0.1uF  [0201]
C225  10pF  [0201]
C226  0.1uF  [0201]
C227  0.1uF  [0201]
C228  0.1uF  [0201]
C229  12pF  [0201]
C230  .1uF  [0201]
C231  .1uF  [0201]
C383  .01uF  [0201]
C384  .01uF  [0201]
C445  TBD  [0201]
C446  TBD  [0201]
C447  TBD  [0201]
C448  TBD  [0201]
FB1  120  [0402]
J12  SMA_THVT_REC  [SMA_THVT_312x312]
JP6  HDR 1x2 2mm  [HDR_THVT_1x2_79_M]
L18  0 ohm  [0402]
L19  0 ohm  [0402]
R71  120  [0201]
R72  120  [0201]
R73  24.9k  [0201]
R74  100  [0201]
R75  100  [0201]
R76  39k  [0201]
R77  240  [0201]
R78  240  [0201]
R79  200  [0201]
R80  200  [0201]
R81  100  [0201]
R82  100  [0201]
R85  0  [0201]
R86  0  [0201]
R87  620  [0201]
R89  240  [0201]
R90  240  [0201]
R93  49.9  [0402]
R94  120  [0201]
R95  120  [0201]
R96  0  [0201]
R99  0  [0201]
R100  200  [0201]
R101  200  [0201]
R102  100  [0201]
R103  100  [0201]
R104  130  [0201]
R105  240  [0201]
R106  240  [0201]
R107  100  [0201]
R108  82  [0201]
R109  49.9  [0201]
R110  240  [0201]
R111  240  [0201]
R112  130  [0201]
R113  100  [0201]
R114  82  [0201]
R115  0  [0201]
R116  49.9  [0201]
R117  240  [0201]
R118  0  [0201]
R119  240  [0201]
R120  240  [0201]
R121  240  [0201]
R234  100  [0201]
R359  0  [0402]
SHN10  SHUNT, JUMPER 2mm
U7  LMK04828  [QFN_64_360X360_0P50MM_PWRPAD]  (sections A,B)
Y1  122.88MHz  [VCXO_6_CUSTOM]
sheet SHEET 09 - LMK POWER & CONF
C232  1uF  [0402]
C233  .1uF  [0201]
C234  0.01uF  [0201]
C235  1uF  [0402]
C236  1uF  [0402]
C237  1uF  [0402]
C238  1uF  [0402]
C239  .1uF  [0201]
C240  0.01uF  [0201]
C241  .1uF  [0201]
C242  10uF  [0402]
C243  1uF  [0402]
C244  1uF  [0402]
D2  LED GREEN  [LED_0603]
D3  LED GREEN  [LED_0603]
D4  LED GREEN  [LED_0603]
D5  LED GREEN  [LED_0603]
FB2  120  [0402]
FB3  120  [0402]
FB4  120  [0402]
FB5  120  [0402]
FB6  120  [0402]
FB7  120  [0402]
FB8  120  [0402]
FB9  120  [0402]
FB10  120  [0402]
FB11  120  [0402]
J13  SMP CONN  [smp_b120]
R122  1.3k  [0201]
R123  0  [0402]
R124  750  [0402]
R125  750  [0402]
R126  750  [0402]
R127  750  [0402]
sheet SHEET 10 - FMC CONN
D6  LED GREEN  [LED_0603]
D7  LED GREEN  [LED_0603]
J14  CON_SMVT_40x10_SEAM  [CON_SMVT_40X10_SEAM_MTG]  (sections A,B,C)
PP34  PROBE POINT  [PROBE_POINT_30PAD]
PP35  PROBE POINT  [PROBE_POINT_30PAD]
PP36  PROBE POINT  [PROBE_POINT_30PAD]
PP37  PROBE POINT  [PROBE_POINT_30PAD]
PP38  PROBE POINT  [PROBE_POINT_30PAD]
PP39  PROBE POINT  [PROBE_POINT_30PAD]
PP41  PROBE POINT  [PROBE_POINT_30PAD]
PP42  PROBE POINT  [PROBE_POINT_30PAD]
PP43  PROBE POINT  [PROBE_POINT_30PAD]
PP44  PROBE POINT  [PROBE_POINT_30PAD]
PP45  PROBE POINT  [PROBE_POINT_30PAD]
PP46  PROBE POINT  [PROBE_POINT_30PAD]
PP47  PROBE POINT  [PROBE_POINT_30PAD]
PP48  PROBE POINT  [PROBE_POINT_30PAD]
PP49  PROBE POINT  [PROBE_POINT_30PAD]
PP50  PROBE POINT  [PROBE_POINT_30PAD]
PP51  PROBE POINT  [PROBE_POINT_30PAD]
Q1  DTC114EET1G  [SOT_416_3_63x31]
Q2  DTC114EET1G  [SOT_416_3_63x31]
R128  1K  [0402]
R129  0  [0402]
R131  1K  [0402]
R132  0  [0402]

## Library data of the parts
C1 = CAP_NP_1: Mfr_Name: MURATA; Mfr_Part_Number: GRM155R71H103KA88D; TOL: 10%; VOLTAGE: 50V
C7 C9 C32-C42 C45 C46 C49 C50 C53 C54 C57 C58 C61 C62 C65 C66 C69 C70 C73 C74 C77 C78 C81 C82 C85 C86 C88 C91 C92 C96 C99 C100 C103 C106-C109 = CAP0402_0: Mfr_Name: TDK; Mfr_Part_Number: C0603X7S1A104K030BC; TOL: 10%; Voltage: 10V
C10-C25 C157 = CAP0402_0: Mfr_Name: MURATA; Mfr_Part_Number: GRM033R61A104KE15D; TOL: 10%; Voltage: 10V
C26 C27 = CAPACITOR_NP_1: Mfr_Name: Yageo; Mfr_Part_Number: CC0402KRX7R7BB562; TOL: 10%; Voltage: 16V
C112-C122 C128-C134 C139 C142 C143 C146 C147 C360 C361 C423 C424 = CAP0402_0: Mfr_Name: MURATA; Mfr_Part_Number: GRM033R61A104KE15D; TOL: 10%; Voltage: 16V
HS1 = HEATSINK_1: Mfr_Name: SVT; Mfr_Part_Number: 10-1003850
J1 = TMP_122841: Mfr_Name: Cinch Connectivity Solutions Johnson; Mfr_Part_Number: 142-0721-841; TI_Silktext: DACCLK
J3 = TMP_122841: Mfr_Name: Cinch Connectivity Solutions Johnson; Mfr_Part_Number: 142-0721-841; TI_Silktext: IOUTA
J4 = TMP_122841: Mfr_Name: Cinch Connectivity Solutions Johnson; Mfr_Part_Number: 142-0721-841; TI_Silktext: IOUTB
R1 = RES0603: Mfr_Name: Panasonic; Mfr_Part_Number: ERJ-1GEF17R8C; TOL: 1%; Wattage: 1/20W
R2 R3 = RES0603: Mfr_Name: Panasonic; Mfr_Part_Number: ERJ-1GEF2940C; TOL: 1%; Wattage: 1/20W
R16 R17 R63 R331 = R: Mfr_Name: PANASONIC; Mfr_Part_Number: ERJ-1GN0R00C; TOL: 5%
R20 R23 R239 = Res_0402_10_H: Mfr_Part_Number: ERJ-2GE0R00X; Note: <Note>
R21 R22 R24 R25 R359 = R: Mfr_Name: PANASONIC; Mfr_Part_Number: ERJ-2GE0R00X; Note: DNI; TOL: 5%
TP1 TP2 TP6 = TESTPOINT_BLK
U1 = DAC38RF80_10x10: Mfr_Part_Number: DAC38RF80IAAV
C28 = CAP_0402_0.001uF_H
C29 C233 C239 C241 = CAPACITOR_NP_1: Mfr_Name: MURATA; Mfr_Part_Number: GRM033R61A104KE15D; TOL: 10%; Voltage: 10V
J5 = Header_2x5_100_0: Mfr_Name: Harwin Inc.; Mfr_Part_Number: M22-2520505; Note: OPEN; TI_SILKTEXT: DAC JTAG
JP1 = Jumper_1x3_100_0: Mfr_Name: Harwin Inc.; Mfr_Part_Number: M22-2510305; Note: (SHUNT 2-3); TI_Silktext: SLEEP
JP2 = Jumper_1x3_100_0: Mfr_Name: Harwin Inc.; Mfr_Part_Number: M22-2510305; Note: (SHUNT 1-2); TI_Silktext: TXENABLE
R30 = R_0: Mfr_Name: Panasonic; Mfr_Part_Number: ERJ-2RKF1001X; PART_NUMBER: Panasonic ERJ-2RKF1001X; TOL: 1%
R31 = Res_0402_1.8K: Mfr_Part_Number: ERJ-1GEF3651C
R129 R132 R230-R233 = Res_0603_Zero_H: Mfr_Part_Number: ERJ-2GE0R00X
SHN9-SHN14 = SHUNT_HEADER: Mfr_Name: Sullins; Mfr_Part_Number: NPN02SXLN-RC
SW1 = SPST_EVQ-PJ: Mfr_Part_Number: EVQ-PNF04M; TI_SILKTEXT: DAC_RESET
TP3 = TESTPOINT_BLUE: Mfr_Part_Number: 5004; TI_SILKTEXT: ALARM
TP15 = TESTPOINT_BLUE: Mfr_Part_Number: 5004; TI_SILKTEXT: ATEST
C30 C43 C47 C51 C55 C59 C63 C67 C71 C75 C79 C83 C89 C93 C95 C97 C101 C104 = CAP0201_0: CLASS: DISCRETE; Mfr_Name: TDK CORP; Mfr_Part_Number: C1608X7S0J106M080AC; TOL: 20%; VOLTAGE: 6.3V
C31 C48 C52 C56 C60 C64 C68 C72 C76 C80 C84 C87 C90 C94 C98 C102 C105 = CAPACITOR_NP_1: Mfr_Name: Yageo; Mfr_Part_Number: CC0402KRX7R5BB105; TOL: 10%; Voltage: 6.3V
C44 = CAPACITOR_NP_1: Mfr_Name: Yageo; Mfr_Part_Number: CC0402KRX7R5BB105; TOL: 20%; Voltage: 6.3V
C110 C111 C123-C127 C135-C138 C140 C141 C148-C150 = CAP_0201_0.1uF: Mfr_Name: MURATA; Mfr_Part_Number: GRM033R61A104KE15D; TOL: 10%; Voltage: 16V
C153 = CAP_NP_0: Mfr_Name: MURATA; Mfr_Part_Number: GRM155R71E103JA01J; TOL: 5%; VOLTAGE: 25V
C154 = CAP0603: Mfr_Name: MURATA; Mfr_Part_Number: GRM155R71C104KA88D; TOL: 10%; Voltage: 16V
C170 C171 C181 C184 C207 C208 C427-C434 = CAP_0603_100pF_H: Mfr_Name: Murata; Mfr_Part_Number: GJM0336C1E100GB01D
J8 = SMP_PLUG_SMT_0: TI_Silktext: ADC_EXT_CLK
JP3 JP7 JP8 = Jumper_1x3_100_0: Mfr_Name: Harwin Inc.; Mfr_Part_Number: M22-2510305; Note: (SHUNT 1-2); TI_Silktext: RF SW
R38 R39 R213-R216 = R_1: CLASS: DISCRETE; Mfr_Name: PANASONIC; Mfr_Part_Number: ERJ-2RKF1002X; TOL: 1%; VOLTAGE: 1/10W
R45 = Res_0201_200_H: Mfr_Part_Number: ERJ-1GEF1000C; Note: DNI; TOL: 1%
R83 R84 R93 = Res_0402_49.9: Mfr_Part_Number: ERJ-2RKF49R9X
R51 R53 R228 R229 = R: Mfr_Name: PANASONIC; Mfr_Part_Number: ERJ-1GN0R00C; Note: DNI; TOL: 5%
T3-T7 = BALUN_TC1-1-43X+
U2 = ADC32RFXX_72QFN: Mfr_Name: Texas Instruments; Mfr_Part_Number: ADC32RF80IRMPT
U3 U4 U27-U30 = RF_SWITCH_MASW_009444: Mfr_Part_Number: MASW-009444-TR3000
C144 C145 = CAP0402_0: Mfr_Name: TDK; Mfr_Part_Number: C0603X5R1A103K030BA; TOL: +/-10%; Voltage: 10V
C158 C162 C163 C167 = CAP_0603_0.1uF_H: Mfr_Name: MURATA; Mfr_Part_Number: GRM188R71C104KA01D; Note: DNI; TOL: 10%; Voltage: 16V
C159 C160 C164 C166 = CAP_0603_0.1uF_H: Mfr_Name: MURATA; Mfr_Part_Number: GRM155R71C104KA88D; TOL: 10%; Voltage: 16V
C161 C165 = CAP_0603_0.1uF_H: Mfr_Name: MURATA; Mfr_Part_Number: GRM155R71C104KA88D; Note: DNI; TOL: 10%; Voltage: 16V
CONN HOUS 2POS .100 = MechPart: Distributed by: Digi Key; Distributor Part #: 277-1011-ND; Mfr_Name: Molex; Mfr_Part_Number: 22-01-3027; Note: For fan wires assembly; use crimp terminal 0008500114
HS2 = HEATSINK_2: Mfr_Name: SVT Heatsink; Mfr_Part_Number: 99-1005601; Note: Soldered to bottom side of DUT
J9 = SMA-END_PLUG_ROUND: Mfr_Name: Cinch Connectivity Solutions Johnson; Mfr_Part_Number: 142-0721-841; TI_Silktext: AIN
J10 = SMA-END_PLUG_ROUND: Mfr_Name: Cinch Connectivity Solutions Johnson; Mfr_Part_Number: 142-0721-841; TI_Silktext: BIN
J38 = HEADER_2_SM: Mfr_Name: Molex; Mfr_Part_Number: 0022112022
JP4 = Jumper_1x3_100_0: Mfr_Name: Harwin Inc.; Mfr_Part_Number: M22-2510305; Note: (SHUNT 2-3); TI_Silktext: PDN
PP27 = PROBE_POINT_2: TI_Silktext: GPIO2
PP28 = PROBE_POINT_2: TI_Silktext: GPIO1
PP29 = PROBE_POINT_2: TI_Silktext: CTRL1
PP30 = PROBE_POINT_2: TI_Silktext: CTRL2
R47 = R_0: Mfr_Name: PANASONIC; Mfr_Part_Number: ERJ-1GEF1001C; TOL: 1%
R49 R50 = R_0: CLASS: DISCRETE; Mfr_Name: PANASONIC; Mfr_Part_Number: ERJ-1GEF1002C; TOL: 1%
R52 = Res_0201_H: Mfr_Name: Panasonic; Mfr_Part_Number: ERJ-1GEJ101C; Note: DNI; PART_NUMBER: ERJ-1GEF101C; TOL: 1%; Wattage: 1/20W
R54-R57 = Res_0603_Zero_H_DNI: Mfr_Part_Number: ERJ-3GEY0R00V
SW2 = SPST_EVQ-PJ: Mfr_Part_Number: EVQ-PNF04M; TI_SILKTEXT: ADC_RESET
TP5 = TESTPOINT_RED: TI_SILKTEXT: VCMOUT
Z_BOARD1 = BARE_BOARD: Mfr_Part_Number: TSW40RF80 rev C
C168 C178 = CAP_0603_100pF_H: Mfr_Name: Murata; Mfr_Part_Number: GRM0335C1E101JA01D
C172 C173 C176 C177 C179 C180 C182 C185 C199 C201 C216 C217 C223 C224 C226 C230 C231 = CAPACITOR_NP_1: Mfr_Name: MURATA; Mfr_Part_Number: GRM033R61A104KE15D; TOL: 10%; Voltage: 16V
C174 C183 C187 C189 = CAP_NP_0: Mfr_Name: Samsung; Mfr_Part_Number: CL03A105MP3NSNC; TOL: 20%; VOLTAGE: 10V
C186 C188 C190 C191 = CAP_NP_1: Mfr_Name: Samsung; Mfr_Part_Number: CL05A106MP5NUNC; TOL: 10%; VOLTAGE: 10V
C192 = CAP_NP_0: Mfr_Name: MURATA; Mfr_Part_Number: GRM033R71E561KA01D; TOL: 10%; VOLTAGE: 25V
C193 = CAP_NP_0: Mfr_Name: Murata; Mfr_Part_Number: GRM033R61C473KE84D; TOL: 10%; VOLTAGE: 16V
C194 = CAP_NP_0: Mfr_Name: Murata; Mfr_Part_Number: GRM033R71A682KA01D; Note: DNI; TOL: 10%; VOLTAGE: 10V
C195 = CAP_NP_0: Mfr_Name: Murata; Mfr_Part_Number: GRM033R71A682KA01D; TOL: 10%; VOLTAGE: 10V
D1 = LED: Mfr_Name: LITE ON; Mfr_Part_Number: LTST-S270KGKT; TI_Silktext: MUXout
JP5 = HDR_2x1_100: Mfr_Name: Harwin Inc.; Mfr_Part_Number: M22-2010205; Note: OPEN; TI_Silktext: LMX PD
R58 R59 R61 R62 = Res_0402_49.9: Mfr_Part_Number: ERJ-1GEF49R9C; TOL: 1%; Wattage: 1/20W
R60 = Res_0402_18: Mfr_Part_Number: ERJ-2RKF1202X
R64 = Res_0402_49.9: Mfr_Part_Number: ERJ-1GEF6800C; Note: DNI; TOL: 1%; Wattage: 1/20W
R67 = Res_0402_49.9: Mfr_Part_Number: ERJ-1GEF6800C; TOL: 1%; Wattage: 1/20W
R68 R85 R86 R96 R99 R115 R118 = Res_0402_Zero_H_DNI: Mfr_Part_Number: ERJ-1GN0R00C
R69 = Res_0402_18: Mfr_Part_Number: ERJ-1GEF12R0C
R70 = R_1: CLASS: DISCRETE; Mfr_Name: PANASONIC; Mfr_Part_Number: ERJ-1GEJ151C; TOL: 1%
U5 = LMX2582_LM2592_1: Mfr_Name: Texas Instruments; Mfr_Part_Number: LMX2582RHAT
C196 C197 = CAP_NP_1: Mfr_Name: MURATA; Mfr_Part_Number: GRM033R61A104KE15D; TOL: 10%; VOLTAGE: 16V
C198 = CAP_NP_0: Mfr_Name: TDK; Mfr_Part_Number: C1005X7S0J684K050BC; TOL: 10%; VOLTAGE: 6.3V
C200 C228 = CAP_NP_0: Mfr_Name: MURATA; Mfr_Part_Number: GRM033R61A104KE15D; TOL: 10%; VOLTAGE: 16V
C202 = CAP_NP_0: Mfr_Name: AVX; Mfr_Part_Number: 0201ZD392KAT2A; TOL: 10%; VOLTAGE: 10V
C203 = CAP_NP_0: Mfr_Name: MURATA; Mfr_Part_Number: GRM0335C1E470JA01D; TOL: 5%; VOLTAGE: 25V
C204 C206 = CAP_0402_0.01uF_H: Mfr_Name: TDK; Mfr_Part_Number: C0603X7S1A104K030BC; TOL: 10%; VOLTAGE: 10V
C218 C227 = CAP_0402_0.1uF_H: Mfr_Part_Number: GRM033R61A104KE15D; TOL: 10%; Voltage: 16V
C219 = CAP_0603_100pF_H: Mfr_Name: Murata; Mfr_Part_Number: GRM033R71E101KA01D
C220 = CAP_0402_0.1uF_H: Mfr_Part_Number: GRM033R61A104KE15D; Note: DNI; TOL: 10%; Voltage: 16V
C221 = CAP_NP_0: Mfr_Name: MURATA; Mfr_Part_Number: GRM033R61A104KE15D; Note: DNI; TOL: 10%; VOLTAGE: 16V
C222 = CAP_0402_2200pF_H: Mfr_Part_Number: GRM033R71C222KA88D
C225 = CAP_0402_10pF_H: Mfr_Part_Number: GJM0336C1E100GB01D
C229 = CAPACITOR_NP_1: Mfr_Name: MURATA; Mfr_Part_Number: GRM0335C1E120JA01D; TOL: 2%; Voltage: 25V
C383 C384 = CAP_0402_0.01uF_H: Mfr_Part_Number: GRM033R71A103KA01D; TOL: 10%; VOLTAGE: 10V
C445-C448 = CAP_0603_100pF_H: Mfr_Name: Murata; Note: DNI
FB1-FB11 = FERRITE_BEAD_0402_H: Isat: 500mA; Mfr_Name: Taiyo Yuden; Mfr_Part_Number: BKP1005HS121-T
J12 = SMA-THVT_142-0701-201_REC: TI_Silktext: LMK_CLKIN
JP6 = HDR_2x1_100: Mfr_Name: Harwin Inc.; Mfr_Part_Number: M22-2010205; Note: SHUNT 1-2
L18 L19 = CHOKE: Mfr_Name: Panasonic; Mfr_Part_Number: ERJ-2GE0R00X
R71 R72 R94 R95 = Res_0402_249: Mfr_Part_Number: ERJ-1GEF1200C
R73 = Res_0402_24.9: Mfr_Part_Number: ERJ-1GEF2492C; Note: DNI
R74 R75 R81 R82 R234 = Res_0402_Zero_H_DNI: Mfr_Part_Number: ERJ-1GEF1000C
R76 = R_1: CLASS: DISCRETE; Mfr_Name: PANASONIC; Mfr_Part_Number: ERJ-1GEF3902C; TOL: 1%
R77 R78 R89 R90 R105 R106 R110 R111 R117 R119 = Res_0402_249: Mfr_Part_Number: ERJ-1GEF2400C; Note: DNI
R79 R80 = Res_0402_249: Mfr_Part_Number: ERJ-1GEF2000C
R87 = R_1: CLASS: DISCRETE; Mfr_Name: PANASONIC; Mfr_Part_Number: ERJ-1GEF6200C; TOL: 1%
R100 R101 = Res_0402_249: Mfr_Part_Number: ERJ-1GEF2000C; Note: DNI
R102 R103 = Res_0603_100: Mfr_Part_Number: ERJ-1GEF1000C; Note: DNI
R104 R112 = RESISTOR_0: CLASS: DISCRETE; Mfr_Name: Panasonic; Mfr_Part_Number: ERJ-1GEF1300C; Note: DNI; TOL: 1%; Wattage: 1/20W
R107 = Res_0402_100_H: Mfr_Part_Number: ERJ-1GEF1000C; Note: DNI
R108 R114 = RESISTOR_0: CLASS: DISCRETE; Mfr_Name: Panasonic; Mfr_Part_Number: ERJ-1GEF82R0C; Note: DNI; TOL: 1%; Wattage: 1/20W
R109 = RESISTOR_0: CLASS: DISCRETE; Mfr_Name: PANASONIC; Mfr_Part_Number: ERJ-1GEF49R9C; Note: DNI; TOL: 1%; Wattage: 1/20W
R113 = Res_0402_100_H: Mfr_Part_Number: ERJ-1GEF1000C
R116 = RESISTOR_0: CLASS: DISCRETE; Mfr_Name: PANASONIC; Mfr_Part_Number: ERJ-1GEF49R9C; TOL: 1%; Wattage: 1/20W
R120 R121 = Res_0402_249: Mfr_Part_Number: ERJ-1GEF2400C
U7 = LMK04828: Mfr_Name: Texas Instruments; Mfr_Part_Number: LMK04828BISQ/NOPB
Y1 = OSC_SM_6_TCO-2100-SERIES_2: Mfr_Name: Crystek; Mfr_Part_Number: CVHD-950-122.880
C232 C235-C238 C243 C244 = CAPACITOR_NP_1: Mfr_Name: Murata; Mfr_Part_Number: GRM155R61A105KE15D; TOL: 10%; Voltage: 10V
C234 C240 = CAPACITOR_NP_1: Mfr_Name: MURATA; Mfr_Part_Number: GRM033R71A103KA01D; TOL: 10%; Voltage: 10V
C242 = CAP_NP_2: CLASS: DISCRETE; Mfr_Name: Samsung; Mfr_Part_Number: CL05A106MP5NUNC; TOL: 20%; VOLTAGE: 10V
D2 = LED: Mfr_Name: LITE ON; Mfr_Part_Number: LTST-S270KGKT; TI_Silktext: STAT 0
D3 = LED: Mfr_Name: LITE ON; Mfr_Part_Number: LTST-S270KGKT; TI_Silktext: STAT 1
D4 = LED: Mfr_Name: LITE ON; Mfr_Part_Number: LTST-S270KGKT; TI_Silktext: LMK LOCKED
D5 = LED: Mfr_Name: LITE ON; Mfr_Part_Number: LTST-S270KGKT; TI_Silktext: PLL2 LOCKED
J13 = SMP_PLUG_SMT_0: TI_Silktext: LMK_SYNC
R122 = RESISTOR_0: CLASS: DISCRETE; Mfr_Name: Panasonic; Mfr_Part_Number: ERJ-1GEF1301C
R123 = R: Mfr_Name: PANASONIC; Mfr_Part_Number: ERJ-2GE0R00X; TOL: 5%
R124-R127 = RESISTOR_0: CLASS: DISCRETE; Mfr_Name: Panasonic; Mfr_Part_Number: ERJ-2RKF7500X
D6 = LED: CLASS: DISCRETE; Mfr_Name: Lite-On; Mfr_Part_Number: LTST-C191KGKT; TI_SILKTEXT: JESD_SYNC
D7 = LED: CLASS: DISCRETE; Mfr_Name: Lite-On; Mfr_Part_Number: LTST-C191KGKT; TI_SILKTEXT: SPARE_LED1
J14 = CON_SMVT_40X10_ASP-134487-01: Mfr_Part_Number: SEAM-40-02.0-S-10-2-A-K-TR
PP34-PP39 PP41-PP51 = PROBE_POINT_2: TI_Silktext: +3.3VCLK
Q1 Q2 = MMBT2222A: Mfr_Name: ON Semiconductor
R128 R131 = R: Mfr_Name: PANASONIC; Mfr_Part_Number: ERJ-2RKF1001X; TOL: 1%; VOLTAGE: 1/10W

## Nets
+1.8V_ANA: C71.1 C72.2 C73.1 C74.1 C75.1 C76.2 C77.1 C78.1 U1.G11(VDDA18) U1.G12(VDDOUT18) U1.H11(VDDA18) U1.H12(VDDOUT18) ; also on sheet 13
+1.8V_CLK: C79.1 C80.2 C81.1 C82.1 C101.1 C102.2 C103.1 U1.B7(VDDTX18) U1.B9(VDDAPLL18) U1.B10(VDDAPLL18) ; also on sheet 13
+1.8V_DIG: C89.1 C90.2 C91.1 C92.1 C93.1 C94.2 C96.1 C97.1 C98.2 C99.1 C100.1 JP1.1(Pin1) JP2.1(Pin1) R30.1 U1.B3(VDDS18) U1.B4(VDDS18) U1.H2(VDDR18) U1.H5(VDDIO18) U1.J2(VDDR18) ; also on sheet 13
+1.8V_VDDVCO: C83.1 C84.2 C85.1 C86.1 U1.D9(VDDAVCO18) U1.E9(VDDAVCO18) ; also on sheet 13
+3.3V_LMX: C172.1 C173.1 C174.2 C176.1 C179.1 C180.2 C185.1 C187.2 R60.2 U5.7(VccDIG) U5.11(VccCP) U5.15(VccDIV) U5.21(VccBUF) U5.26(VccDBLR) U5.37(VccVCO) ; also on sheet 11
+3.3V_LMXRF: C139.1 C168.1 C178.1 C423.1 C424.1 R38.1 R39.1 R58.2 R59.2 R61.2 R62.2 R213.1 R214.1 R215.1 R216.1 ; also on sheet 11
+3.3VCLK: FB2.1 FB3.1 FB4.1 FB5.1 FB6.1 FB10.1 FB11.1 JP6.2 R73.1 R104.1 R112.1 R359.1 ; also on sheet 11
+5VIN: D6.1(ANODE) D7.1(ANODE) J38.1 ; also on sheet 11 12 13 15
-1.8V_VEE: C104.1 C105.2 C106.1 C107.1 C108.1 C109.1 U1.D10(VEEB_-1.8V) U1.E10(VEEB_-1.8V) U1.K10(VEEA_-1.8V) U1.L10(VEEA_-1.8V) ; also on sheet 12
AVDD1.9V: C142.1 C143.1 C144.1 C145.1 C146.1 C147.1 U2.10(AVDD19) U2.16(AVDD19) U2.24(AVDD19) U2.31(AVDD19) U2.39(AVDD19) U2.45(AVDD19) ; also on sheet 14
AVDD1.15V: C112.1 C113.1 C114.1 C115.1 C116.1 C117.1 C118.1 C119.1 C120.1 C121.1 C122.1 U2.9(AVDD) U2.12(AVDD) U2.15(AVDD) U2.17(AVDD) U2.25(AVDD) U2.30(AVDD) U2.38(AVDD) U2.40(AVDD) U2.43(AVDD) U2.44(AVDD) U2.46(AVDD) ; also on sheet 14
DVDD1.15V: C128.1 C129.1 C130.1 C131.1 C132.1 C133.1 C134.1 JP4.1(Pin1) R47.2 U2.4(DVDD) U2.8(DVDD) U2.47(DVDD) U2.51(DVDD) U2.57(DVDD) U2.64(DVDD) U2.70(DVDD) ; also on sheet 14 15
DVDD_1P0V: C30.1 C31.2 C32.1 C33.1 C34.1 C35.1 C36.1 C37.1 C38.1 C39.1 C40.1 C41.1 C42.1 U1.A5(VDD_1V) U1.B5(VDD_1V) U1.C5(VDD_1V) U1.D5(VDD_1V) U1.D7(VDD_1V) U1.E3(VDD_1V) U1.E4(VDD_1V) U1.E5(VDD_1V) U1.E6(VDD_1V) U1.F4(VDD_1V) U1.F5(VDD_1V) U1.G4(VDD_1V) U1.G5(VDD_1V) ; also on sheet 12 13
GND: C28.2 C29.2 C30.2 C31.1 C32.2 C33.2 C34.2 C35.2 C36.2 C37.2 C38.2 C39.2 C40.2 C41.2 C42.2 C43.2 C44.1 C45.2 C46.2 C47.2 C48.1 C49.2 C50.2 C51.2 C52.1 C53.2 C54.2 C55.2 C56.1 C57.2 C58.2 C59.2 C60.1 C61.2 C62.2 C63.2 C64.1 C65.2 C66.2 C67.2 C68.1 C69.2 C70.2 C71.2 C72.1 C73.2 C74.2 C75.2 C76.1 C77.2 C78.2 C79.2 C80.1 C81.2 C82.2 C83.2 C84.1 C85.2 C86.2 C87.1 C88.2 C89.2 C90.1 C91.2 C92.2 C93.2 C94.1 C95.2 C96.2 C97.2 C98.1 C99.2 C100.2 C101.2 C102.1 C103.2 C104.2 C105.1 C106.2 C107.2 C108.2 C109.2 C112.2 C113.2 C114.2 C115.2 C116.2 C117.2 C118.2 C119.2 C120.2 C121.2 C122.2 C128.2 C129.2 C130.2 C131.2 C132.2 C133.2 C134.2 C139.2 C142.2 C143.2 C144.2 C145.2 C146.2 C147.2 C154.2 C157.2 C159.1 C161.1 C165.1 C166.1 C168.2 C172.2 C173.2 C174.1 C176.2 C177.1 C178.2 C179.2 C180.1 C182.2 C183.1 C185.2 C186.1 C187.1 C188.1 C189.1 C190.1 C191.1 C192.2 C194.2 C195.2 C200.2 C203.2 C206.1 C218.1 C219.1 C222.1 C223.1 C225.1 C229.1 C232.1 C233.1 C234.1 C235.1 C236.1 C237.1 C238.1 C239.1 C240.1 C241.2 C242.2 C243.1 C244.1 C423.2 C424.2 C445.1 C446.1 C447.1 C448.1 D1.2(CATHODE) D2.2(CATHODE) D3.2(CATHODE) D4.2(CATHODE) D5.2(CATHODE) HS1.MTG1 HS1.MTG2 HS2.1 HS2.2 J1.2(GND) J1.3(GND) J1.4(GND) J1.5(GND) J3.2(GND) J3.3(GND) J3.4(GND) J3.5(GND) J4.2(GND) J4.3(GND) J4.4(GND) J4.5(GND) J8.2(SHIELD1) J9.2(SHIELD3) J9.3(SHIELD4) J9.4(SHIELD1) J9.5(SHIELD2) J10.2(SHIELD3) J10.3(SHIELD4) J10.4(SHIELD1) J10.5(SHIELD2) J12.2(GND) J12.3(GND) J12.4(GND) J12.5(GND) J13.2(SHIELD1) J14.A1 J14.A4 J14.A5 J14.A8 J14.A9 J14.A12 J14.A13 J14.A16 J14.A17 J14.A20 J14.A21 J14.A24 J14.A25 J14.A28 J14.A29 J14.A32 J14.A33 J14.A36 J14.A37 J14.A40 J14.B2 J14.B3 J14.B6 J14.B7 J14.B10 J14.B11 J14.B14 J14.B15 J14.B18 J14.B19 J14.B22 J14.B23 J14.B26 J14.B27 J14.B30 J14.B31 J14.B34 J14.B35 J14.B38 J14.B39 J14.C1 J14.C4 J14.C5 J14.C8 J14.C9 J14.C12 J14.C13 J14.C16 J14.C17 J14.C20 J14.C21 J14.C24 J14.C25 J14.C28 J14.C29 J14.C32 J14.C33 J14.C36 J14.C38 J14.C40 J14.D2 J14.D3 J14.D6 J14.D7 J14.D10 J14.D13 J14.D16 J14.D19 J14.D22 J14.D25 J14.D28 J14.D37 J14.D39 J14.E1 J14.E4 J14.E5 J14.E8 J14.E11 J14.E14 J14.E17 J14.E20 J14.E23 J14.E26 J14.E29 J14.E32 J14.E35 J14.E38 J14.E40 J14.F3 J14.F6 J14.F9 J14.F12 J14.F15 J14.F18 J14.F21 J14.F24 J14.F27 J14.F30 J14.F33 J14.F36 J14.F39 J14.G1 J14.G4 J14.G5 J14.G8 J14.G11 J14.G14 J14.G17 J14.G20 J14.G23 J14.G26 J14.G29 J14.G32 J14.G35 J14.G38 J14.G40 J14.H3 J14.H6 J14.H9 J14.H12 J14.H15 J14.H18 J14.H21 J14.H24 J14.H27 J14.H30 J14.H33 J14.H36 J14.H39 J14.J1 J14.J4 J14.J5 J14.J8 J14.J11 J14.J14 J14.J17 J14.J20 J14.J23 J14.J26 J14.J29 J14.J32 J14.J35 J14.J38 J14.J40 J14.K2 J14.K3 J14.K6 J14.K9 J14.K12 J14.K15 J14.K18 J14.K21 J14.K24 J14.K27 J14.K30 J14.K33 J14.K36 J14.K39 J38.2 JP1.3(Pin3) JP2.3(Pin3) JP3.2(Pin2) JP4.3(Pin3) JP5.1 JP7.2(Pin2) JP8.2(Pin2) Q1.2(E) Q2.2(E) R2.2 R3.2 R21.2 R22.2 R24.2 R25.2 R31.2 R49.1 R50.1 R67.1 R70.2 R71.2 R72.2 R76.2 R77.2 R78.2 R79.2 R80.2 R81.1 R82.1 R87.2 R89.2 R90.2 R93.2 R94.2 R95.2 R100.2 R101.2 R102.2 R103.2 R105.2 R106.2 R108.2 R109.2 R110.2 R111.2 R114.2 R116.2 R117.2 R119.2 R120.2 R121.2 R122.1 R239.2 R331.1 SW1.1 T3.4(PRI) TP1.1(TP) TP2.1(TP) TP6.1(TP) U1.A2(DGND) U1.A8(VSSCLK) U1.A11(VSSCLK) U1.B2(DGND) U1.B8(VSSCLK) U1.B11(VSSCLK) U1.B12(VSSCLK) U1.C2(DGND) U1.C11(AGNDB) U1.C12(AGNDB) U1.D2(DGND) U1.D6(DGND) U1.D11(AGNDB) U1.D12(VOUTBP) U1.E2(DGND) U1.E7(DGND) U1.E11(AGNDB) U1.F2(DGND) U1.F6(DGND) U1.F8(VSSCLK) U1.F9(VSSCLK) U1.F10(VSSCLK) U1.F12(AGNDB) U1.G2(DGND) U1.G7(DGND) U1.H6(DGND) U1.J7(DGND) U1.J8(VSSCLK) U1.J9(VSSCLK) U1.J10(VSSCLK) U1.J12(AGNDA) U1.K2(DGND) U1.K11(AGNDA) U1.L2(DGND) U1.L3(DGND) U1.L4(DGND) U1.L5(DGND) U1.L11(AGNDA) U1.L12(VOUTAP) U1.M6(DGND) U1.M11(AGNDA) U1.M12(AGNDA) U2.3(DGND) U2.18(AGND) U2.23(AGND) U2.26(AGND) U2.29(AGND) U2.32(AGND) U2.37(AGND) U2.52(DGND) U2.60(DGND) U2.67(DGND) U2.73(THERMALPAD) U3.2(GND) U4.2(GND) U5.2(GND) U5.4(GND) U5.6(GND) U5.13(GND) U5.14(GND) U5.25(GND) U5.31(GND) U5.34(GND) U5.39(GND) U5.40(GND) U5.41(PWRPAD) U7.65(DAP) U27.2(GND) U28.2(GND) U29.2(GND) U30.2(GND) Y1.3(GND) ; also on sheet 11 12 13 14 15
V1: JP3.1(Pin1) R38.2 U29.1(V1) U30.1(V1)
V2: JP3.3(Pin3) R39.2 U29.5(V2) U30.5(V2)
V3: JP7.1(Pin1) R214.2 U27.1(V1) U28.1(V1)
V4: JP7.3(Pin3) R213.2 U27.5(V2) U28.5(V2)
V5: JP8.1(Pin1) R216.2 U3.1(V1) U4.1(V1)
V6: JP8.3(Pin3) R215.2 U3.5(V2) U4.5(V2)
3P3VAUX: J14.D32 PP51.1
+1P0V_ANA: C67.1 C68.2 C69.1 C70.1 U1.F11(VDDAB_1V) U1.J11(VDDAA_1V) ; also on sheet 13
+1P0V_CLK: C51.1 C52.2 C53.1 C54.1 C55.1 C56.2 C57.1 C58.1 C63.1 C64.2 C65.1 C66.1 C87.2 C88.1 C95.1 U1.B6(VDDTX) U1.D8(VDDPLL_1V) U1.E8(VDDPLL_1V) U1.G9(VDDCLK_1V) U1.G10(VDDL2B_1V) U1.H9(VDDCLK_1V) U1.H10(VDDL2A_1V) ; also on sheet 13
+1P0V_DIG: C43.1 C44.2 C45.1 C46.1 U1.F7(VDDE_1V) U1.G6(VDDE_1V) U1.H7(VDDE_1V) U1.J6(VDDE_1V) ; also on sheet 13
+1P0V_VDDL1: C47.1 C48.2 C49.1 C50.1 C59.1 C60.2 C61.1 C62.1 U1.G8(VDDL1B_1V) U1.H3(VDDT_1V) U1.H8(VDDL1A_1V) U1.J3(VDDT_1V) ; also on sheet 13
A_IN: C160.1 J9.1(CENTER)
ADC_CLK: C153.1 J8.1(CENTER)
ADC_CLKINM: C428.2 R229.1 U2.28(CLKINM)
ADC_CLKINP: C427.2 R229.2 U2.27(CLKINP)
ADC_LKXEN: C434.1 U28.6(RFC)
ADC_LKXEP: C433.1 U27.6(RFC)
ADC_LXEN: C432.1 U30.6(RFC)
ADC_LXEP: C431.1 U29.6(RFC)
ADC_RESET: R49.2 SW2.2 U2.48(RESET) ; also on sheet 15
ADC_SCLK: U2.6(SCLK) ; also on sheet 15
ADC_SDIO: U2.5(SDATA) ; also on sheet 15
ADC_SDO: U2.11(SDOUT) ; also on sheet 15
ADC_SEN: U2.7(SEN) ; also on sheet 15
ADC_SYNC_N: J14.G13 U2.36(SYNCBM)
ADC_SYNC_P: J14.G12 U2.35(SYNCBP)
ADC_SYSREFN: R45.1 R99.2 R102.1 U2.34(SYSREFM)
ADC_SYSREFP: R45.2 R96.2 R103.1 U2.33(SYSREFP)
AIN+: C162.1 R55.2 T4.3(SEC) T5.1(SEC_DOT)
AIN-: C158.1 R54.2 T4.1(SEC_DOT) T5.3(SEC)
AINM: C158.2 T5.4(PRI) U2.41(INAM)
AINP: C162.2 T5.6(PRI_DOT) U2.42(INAP)
ALARM: TP3.1(TP) U1.K8(ALARM)
ATEST: TP15.1(TP) U1.C8(ATEST)
B_IN: C164.1 J10.1(CENTER)
BIN+: C163.1 R56.2 T6.1(SEC_DOT) T7.3(SEC)
BIN-: C167.1 R57.2 T6.3(SEC) T7.1(SEC_DOT)
BINM: C167.2 T7.6(PRI_DOT) U2.14(INBM)
BINP: C163.2 T7.4(PRI) U2.13(INBP)
CAR_SYSREF_M: R86.1 R89.1 U7.4(SDCLKOUT1n)
CAR_SYSREF_P: R85.1 R90.1 U7.3(SDCLKOUT1p)
CAR_SYSREFM: J14.G10 R86.2
CAR_SYSREFP: J14.G9 R85.2
CE: JP5.2 R60.1 U5.1(CE)
CLK_LAO_0M: J14.G7 R118.2
CLK_LAO_0P: J14.G6 R115.2
CLKIN0_N: C206.2 U7.38(CLKIN0n)
CLKIN0_P: C204.2 U7.37(CLKIN0p)
CLKIN1N: C384.2 R234.1 U7.35(CLKIN1n/FBCLKINn/FINn)
CLKIN1P: C383.2 R234.2 U7.34(CLKIN1p/FBCLKINp/FINp)
CLKLA_0M: R118.1 R119.1 U7.63(DCLKOUT12n)
CLKLA_0P: R115.1 R117.1 U7.62(DCLKOUT12p)
CP1: C198.1 C200.1 R73.2 U7.32(CPOUT1) Y1.1(VC)
CP2: C202.1 C203.1 U7.46(CPOUT2)
CPout: C192.1 C193.1 R68.1 U5.12(CPout)
DA0N: C111.2 J14.B13
DA0P: C110.2 J14.B12
DA1N: C124.2 J14.A15
DA1P: C123.2 J14.A14
DA2N: C126.2 J14.B17
DA2P: C125.2 J14.B16
DA3N: C135.2 J14.A19
DA3P: C127.2 J14.A18
DAC_ALT_SYNC_N: J14.F20 U1.C6(SYNC1BN)
DAC_ALT_SYNC_P: J14.F19 U1.C7(SYNC1BP)
DAC_CLKOUTN: C9.2 U4.4(RF2)
DAC_CLKOUTP: C7.2 U3.4(RF2)
DAC_RESET: C28.1 R30.2 SW1.2 U1.K9(RESETB) ; also on sheet 15
DAC_SCLK: R232.1 ; also on sheet 15
DAC_SDENB: R231.1 ; also on sheet 15
DAC_SDIO: R230.1 ; also on sheet 15
DAC_SDO: R233.1 ; also on sheet 15
DAC_SYNC_N: J14.F11 U1.C3(SYNC0BN)
DAC_SYNC_P: J14.F10 U1.C4(SYNC0BP)
DACCLK_IN: C1.1 J1.1(CENTER)
DACCLK_N: C361.1 U1.A9(DACCLKN)
DACCLK_P: C360.1 U1.A10(DACCLKP)
DACCLK_SE: C1.2 R1.2 R2.1
DACCLKSE: R1.1 R3.1 U1.A12(DACCLKSE)
DB0N: C137.2 J14.A11
DB0P: C136.2 J14.A10
DB1N: C140.2 J14.C7
DB1P: C138.2 J14.C6
DB2N: C148.2 J14.A7
DB2P: C141.2 J14.A6
DB3N: C150.2 J14.A3
DB3P: C149.2 J14.A2
DCLKOUT2N: C197.1 R72.1 U7.16(DCLKOUT2n)
DCLKOUT2P: C196.1 R71.1 U7.15(DCLKOUT2p)
DCLKOUT4N: C208.1 R95.1 U7.25(DCLKOUT4n)
DCLKOUT4P: C207.1 R94.1 U7.24(DCLKOUT4p)
DP0_C2M_N: C18.1 J14.C3
DP0_C2M_P: C19.1 J14.C2
DP1_C2M_N: C22.1 J14.A23
DP1_C2M_P: C20.1 J14.A22
DP2_C2M_N: C23.1 J14.A27
DP2_C2M_P: C21.1 J14.A26
DP3_C2M_N: C24.1 J14.A31
DP3_C2M_P: C25.1 J14.A30
DP4_C2M_N: C15.1 J14.A35
DP4_C2M_P: C14.1 J14.A34
DP5_C2M_N: C10.1 J14.A39
DP5_C2M_P: C11.1 J14.A38
DP6_C2M_N: C12.1 J14.B37
DP6_C2M_P: C13.1 J14.B36
DP7_C2M_N: C17.1 J14.B33
DP7_C2M_P: C16.1 J14.B32
EXT_ADCCLKINM: C430.1 R84.2 T3.3(SEC)
EXT_ADCCLKINP: C429.1 R83.1 T3.1(SEC_DOT)
EXTIO: C29.1 U1.C10(EXTIO)
FMC_ADC_RESET: J14.D15 ; also on sheet 15
FMC_ADC_SCK: J14.C14 ; also on sheet 15
FMC_ADC_SDIO: J14.C15 ; also on sheet 15
FMC_ADC_SDO: J14.C18 ; also on sheet 15
FMC_ADC_SEN: J14.D14 ; also on sheet 15
FMC_CTRL1: J14.C26 R51.1
FMC_CTRL2: J14.C27 R53.1
FMC_DAC_RESET: J14.E19 ; also on sheet 15
FMC_DAC_SCK: J14.G16 ; also on sheet 15
FMC_DAC_SDENB: J14.H16 ; also on sheet 15
FMC_DAC_SDIO: J14.G15 ; also on sheet 15
FMC_DAC_SDO: J14.H17 ; also on sheet 15
FMC_LMK_CSb: J14.E10 ; also on sheet 15
FMC_LMK_SCK: J14.E6 ; also on sheet 15
FMC_LMK_SDIO: J14.E7 ; also on sheet 15
FMC_LMK_SDO: J14.E9 ; also on sheet 15
FMC_LMX_CSb: J14.E16 ; also on sheet 15
FMC_LMX_SCK: J14.E12 ; also on sheet 15
FMC_LMX_SDIO: J14.E13 ; also on sheet 15
FMC_LMX_SDO: J14.E15 ; also on sheet 15
FPGA_CLK1_N: C217.2 J14.K5
FPGA_CLK1_P: C216.2 J14.K4
FPGA_CLK1N: C217.1 R106.1 U7.52(DCLKOUT8n)
FPGA_CLK1P: C216.1 R105.1 U7.51(DCLKOUT8p)
FPGA_CLK2_N: C226.2 J14.J3
FPGA_CLK2_P: C224.2 J14.J2
FPGA_CLK2N: C226.1 R110.1 U7.50(SDCLKOUT9n)
FPGA_CLK2P: C224.1 R111.1 U7.49(SDCLKOUT9p)
FTDI_TCK: J5.2 ; also on sheet 15
FTDI_TDI: J5.4 ; also on sheet 15
FTDI_TDO: J5.6 ; also on sheet 15
FTDI_TMS: J5.8 ; also on sheet 15
FTDI_TRSTB: J5.10 ; also on sheet 15
GA0: J14.C34 PP36.1
GA1: J14.D35 PP37.1
GPIO1: PP28.1 U2.19(GPIO1)
GPIO2: PP27.1 U2.63(GPIO2)
GTX_CLKM: C201.2 J14.D5
GTX_CLKP: C199.2 J14.D4
GTXCLKM: C201.1 R77.1 U7.2(DCLKOUT0n)
GTXCLKP: C199.1 R78.1 U7.1(DCLKOUT0p)
IOUTA: J3.1(CENTER) R20.1 R22.1
IOUTAM: C26.1 U1.K12(VOUTAM)
IOUTB: J4.1(CENTER) R23.1 R25.1
IOUTBP: C27.1 U1.E12(VOUTBM)
LMK LOCKED: D4.1(ANODE) R126.1
LMK_ADC_CLKN: C448.2 L19.2 U28.4(RF2)
LMK_ADC_CLKP: C447.2 L18.2 U27.4(RF2)
LMK_CLKIN: C204.1 J12.1(CENTER) R93.1
LMK_CSb: U7.18(\\~{CS}) ; also on sheet 15
LMK_DAC_CLKN: C197.2 C361.2
LMK_DAC_CLKP: C196.2 C360.2
LMK_DAC_SYSREFN: R17.1 R74.2 R81.2
LMK_DAC_SYSREFP: R16.1 R75.2 R82.2
LMK_SCK: U7.19(SCK) ; also on sheet 15
LMK_SDIO: U7.20(SDIO) ; also on sheet 15
LMK_SDO: R122.2 U7.5(RESET) ; also on sheet 15
LMX_CLKAN: C171.2 U30.3(RF1)
LMX_CLKAP: C170.2 U29.3(RF1)
LMX_CLKBN: C184.2 C383.1
LMX_CLKBP: C181.2 C384.1
LMX_CSb: U5.24(CSB) ; also on sheet 15
LMX_OSCM: C230.2 U5.9(OSCinM)
LMX_OSCP: C231.2 U5.8(OSCinP)
LMX_SCLK: U5.16(SCK) ; also on sheet 15
LMX_SDI: U5.17(SDI) ; also on sheet 15
LMX_SDO: R63.2 ; also on sheet 15
OSCINN: C228.2 C229.2 U7.44(OSCINn)
OSCINP: C221.2 C223.2 U7.43(OSCINp)
OSCN: C227.2 C228.1 R112.2 R116.1
OSCOUTn: C231.1 R121.1 U7.41(OSCOUTn)
OSCOUTp: C230.1 R120.1 U7.40(OSCOUTp)
OSCP: C220.2 C221.1 R104.2 R109.1
PDN: JP4.2(Pin2) U2.50(PDN)
PG_C2M: J14.D1 PP49.1
PG_M2C: J14.F1 PP48.1
PLL2 LOCKED: D5.1(ANODE) R127.1
PRSNT_M2C_L: J14.H2 PP47.1
RES0: J14.B40 PP50.1
RX0N: C18.2 U1.M4(RXN3)
RX0P: C19.2 U1.M5(RXP3)
RX1N: C22.2 U1.M3(RXN2)
RX1P: C20.2 U1.M2(RXP2)
RX2N: C23.2 U1.L1(RXN1)
RX2P: C21.2 U1.M1(RXP1)
RX3N: C24.2 U1.K1(RXN0)
RX3P: C25.2 U1.J1(RXP0)
RX4N: C15.2 U1.F1(RXN5)
RX4P: C14.2 U1.E1(RXP5)
RX5N: C10.2 U1.B1(RXN7)
RX5P: C11.2 U1.A1(RXP7)
RX6N: C12.2 U1.C1(RXN6)
RX6P: C13.2 U1.D1(RXP6)
RX7N: C17.2 U1.G1(RXN4)
RX7P: C16.2 U1.H1(RXP4)
SCAN_EN: R50.2 U2.49(SCAN_EN)
SCL: J14.C30 PP34.1
SCLK: R232.2 U1.L9(SCLK)
SDA: J14.C31 PP35.1
SDCLKOUT3N: R75.1 R80.1 U7.14(SDCLKOUT3n)
SDCLKOUT3P: R74.1 R79.1 U7.13(SDCLKOUT3p)
SDCLKOUT5N: R99.1 R101.1 U7.23(SDCLKOUT5n)
SDCLKOUT5P: R96.1 R100.1 U7.22(SDCLKOUT5p)
SDENB: R231.2 U1.M8(SDENB)
SDIO: R230.2 U1.M10(SDIO)
SDO: R233.2 U1.M9(SDO)
SLEEP: JP1.2(Pin2) U1.L8(SLEEP)
STAT 0: D2.1(ANODE) R124.1
STAT 1: D3.1(ANODE) R125.1
SYNC: R123.2 U7.6(SYNC)
SYSREF-N: R17.2 U1.A4(SYSREFN)
SYSREF-P: R16.2 U1.A3(SYSREFP)
TCK: J14.D29 PP44.1
TDI: J14.D30 PP43.1
TDO: J14.D31 PP45.1
TMS: J14.D33 PP46.1
TRST_L: J14.D34 PP42.1
TXA0_M: C111.1 U2.62(DA0M)
TXA0_P: C110.1 U2.61(DA0P)
TXA1_M: C124.1 U2.59(DA1M)
TXA1_P: C123.1 U2.58(DA1P)
TXA2_M: C126.1 U2.56(DA2M)
TXA2_P: C125.1 U2.55(DA2P)
TXA3_M: C135.1 U2.54(DA3M)
TXA3_P: C127.1 U2.53(DA3P)
TXB0_M: C137.1 U2.65(DB0M)
TXB0_P: C136.1 U2.66(DB0P)
TXB1_M: C140.1 U2.68(DB1M)
TXB1_P: C138.1 U2.69(DB1P)
TXB2_M: C148.1 U2.71(DB2M)
TXB2_P: C141.1 U2.72(DB2P)
TXB3_M: C150.1 U2.1(DB3M)
TXB3_P: C149.1 U2.2(DB3P)
TXENABLE: JP2.2(Pin2) U1.K6(TXENABLE)
VCM: C157.1 TP5.1(TP) U2.22(VCM)
VIO_B_M2C: J14.J39 J14.K40 PP41.1
VREF_A_M2C: J14.H1 PP38.1
VREF_B_M2C: J14.K1 PP39.1
Y2_N: R113.1 R114.1 Y1.4(OUT_N)
Y2_P: R107.1 R108.1 Y1.5(OUT_P)
YO2_N: C227.1 R113.2
YO2_P: C220.1 R107.2
N17906763: J13.1(CENTER) R123.1
N18864728: Q2.1(B) R132.2
N18864763: J14.D17 R132.1
N18864775: J14.D18 R129.1
N18864798: Q2.3(C) R131.2
N18865554: D7.2(CATHODE) R131.1
N19080738: C218.2 C219.2 C222.2 C225.2 FB1.2 Y1.6(VDD)
N19081029: R359.2 Y1.2(NC)
N19083254: R126.2 U7.31(STATUS_LD1)
N19083268: R127.2 U7.48(STATUS_LD2)
N19083286: R125.2 U7.59(CLKin_SEL1)
N19083328: R124.2 U7.58(CLKin_SEL0)
N19083344: C241.1 U7.12(LDObyp2)
N19083346: C242.1 U7.11(LDObyp1)
N19083364: C232.2 C233.2 C234.2 FB2.2 U7.10(VCC1_VCO) U7.33(VCC5_DIG) U7.36(VCC6_PLL1)
N19083444: FB7.2 U7.39(VCC7_OSCout)
N19083446: FB9.2 U7.45(VCC9_CP2)
N19083508: C238.2 C239.2 C240.2 FB6.2 FB7.1 FB8.1 FB9.1 U7.47(VCC10_PLL2)
N19083566: C236.2 FB3.2 U7.21(VCC3_SYSREF)
N19083568: C235.2 FB5.2 U7.17(VCC2_CG1)
N19083616: C244.2 FB11.2 U7.64(VCC12_CG0)
N19083618: C243.2 FB10.2 U7.53(VCC11_CG3)
N19083707: C237.2 FB4.2 U7.26(VCC4_CG2)
N19234861: FB8.2 U7.42(VCC8_OSCin)
N20060120: C9.1 U1.A6(CLKTXN)
N20060672: C7.1 U1.A7(CLKTXP)
N20072726: C427.1 R228.2 U3.6(RFC)
N20072730: C428.1 R228.1 U4.6(RFC)
N20074990: C166.2 R57.1 T6.4(PRI)
N20074992: C164.2 C165.2 R56.1 T6.6(PRI_DOT)
N20075215: C159.2 R54.1 T4.6(PRI_DOT)
N20075219: C160.2 C161.2 R55.1 T4.4(PRI)
N20076572: D1.1(ANODE) R64.1
N20076618: C186.2 U5.29(VrefVCO)
N20076637: C188.2 U5.36(VrefVCO)
N20076686: C191.2 U5.33(VbiasVARAC)
N20076744: C170.1 R58.1 U5.23(RFoutAP)
N20076746: C171.1 R59.1 U5.22(RFoutAM)
N20076858: C177.2 U5.10(VccIN)
N20076866: C181.1 R61.1 U5.18(RFoutBP)
N20076868: C184.1 R62.1 U5.19(RFoutBM)
N20076920: C193.2 R70.1
N20076959: C194.1 R68.2 R69.1
N20076978: C195.1 R69.2 U5.35(Vtune)
N20077010: R67.2 U5.30(Rext)
N20077268: C182.1 C183.2 U5.27(VbiasBANK)
N20077503: R63.1 R64.2 U5.20(MUXout)
N20087628: R31.1 U1.C9(RBIAS)
N20088284: C27.2 R23.2 R24.1
N20088327: C26.2 R20.2 R21.1
N20165749: C207.2 C445.2 L18.1
N20165751: C208.2 C446.2 L19.1
N20264121: FB1.1 JP6.1
N20413661: PP29.1 R51.2 R52.2 U2.20(CTRL1)
N20413665: PP30.1 R52.1 R53.2 U2.21(CTRL2)
N20414446: R47.1 SW2.1
N20417693: C153.2 T3.6(PRI_DOT)
N20417714: C154.1 T3.2(NC)
N20493705: R83.2 R84.1
N20546375: C189.2 U5.38(VregVCO)
N20546772: C190.2 U5.3(VbiasVCO)
N20556233: J5.1 U1.K4(TCLK)
N20556256: J5.3 U1.H4(TDI)
N20556281: J5.5 U1.J4(TDO)
N20556364: J5.7 U1.K5(TMS)
N20556495: J5.9 R239.1 U1.J5(TRSTB)
N20643618: C429.2 U29.4(RF2)
N20643644: C430.2 U30.4(RF2)
N20643698: C431.2 U27.3(RF1)
N20643721: C432.2 U28.3(RF1)
N20643769: C433.2 U3.3(RF1)
N20643792: C434.2 U4.3(RF1)
N20674238: Q1.1(B) R129.2
N20674280: D6.2(CATHODE) R128.1
N20715968: R331.2 U1.K3(TESTMODE)
N20976463: Q1.3(C) R128.2
N20977104: C202.2 R87.1
N20977105: C198.2 R76.1

Not connected (* = marked no-connect by the designer): J14 B1 B4 B5 B8 B9 B20 B21 B24 B25 B28 B29 C10* C11* C19* C22* C23* C35 C37 C39 D8 D9 D11 D12 D20 D21 D23 D24 D26 D27 D36 D38 D40 E2 E3 E18 E21 E22 E24 E25 E27 E28 E30 E31 E33 E34 E36 E37 E39 F2 F4 F5 F7 F8 F13 F14 F16 F17 F22 F23 F25 F26 F28 F29 F31 F32 F34 F35 F37 F38 F40 G2 G3 G18 G19 G21 G22 G24 G25 G27 G28 G30 G31 G33 G34 G36 G37 G39 H4 H5 H7 H8 H10 H11 H13 H14 H19 H20 H22 H23 H25 H26 H28 H29 H31 H32 H34 H35 H37 H38 H40 J6 J7 J9 J10 J12 J13 J15 J16 J18 J19 J21 J22 J24 J25 J27 J28 J30 J31 J33 J34 J36 J37 K7 K8 K10 K11 K13 K14 K16 K17 K19 K20 K22 K23 K25 K26 K28 K29 K31 K32 K34 K35 K37 K38; T4 2(NC); T5 2(NC); T6 2(NC); T7 2(NC); U1 D3(IFORCE) D4(VSENSE) F3(AMUX1) G3(AMUX0) K7(GPI0) L6(GPO1) L7(GPO0) M7(GPI1); U5 5(NC1) 28(NC2) 32(NC3); U7 7(NC1) 8(NC2) 9(NC3) 27(DCLKOUT6p) 28(DCLKOUT6n) 29(SDCLKOUT7p) 30(SDCLKOUT7n) 54(DCLKOUT10p) 55(DCLKOUT10n) 56(SDCLKOUT11p) 57(SDCLKOUT11n) 60(SDCLKOUT13p) 61(SDCLKOUT13n)

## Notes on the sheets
sheet 1
- ADC32RF45
  DAC38RF80
- LMK
- DACCLK
- USB PORT
- SYSREF
- PAGE 11
- PAGE 8-9
- PAGES 2-6
- LMX
- PAGE 7
- JESD204B
- INTERFACE
- PAGE 10
- POWER SUPPLIES
- PAGE 12-15
- Drawn:
- L NGUYEN     10/2016
- Engineer:
- R. HOPPENSTEIN   10/2016
sheet 2
- NOTES:
  R1, R2, and R3 form 3dB pad by default.
- NOTES:
- 1)  DNI = DO NOT INSTALL
sheet 5
- LMX
- JP3 OUT
- JP7 OUT
- EXT CLK
- LMK
- DACCLK OUT
sheet 6
- Shared pad
- Shared pad
- Shared pad
- Shared pad
- Shared pad
- Shared pad
- Shared pad
- Shared pad
- Shared pad
- Shared pad
- Shared pad
- Shared pad
- Shared pad
- Shared pad
- Shared pad
- Shared pad
sheet 8
- TSW JESD Interface
  reference clock w/
  LVDS levels
- Place near Vc pin of Y1;
  these 2 components form voltage divider
  set the center frequency voltage for PLL2 reference
- MATCHED LENGTH
- MATCHED LENGTH
- Place close to LMK
- MATCHED LENGTH
- MATCHED LENGTH
- Place close to LMK
- JESD CORECLOCK
- Y1 CMOS version OUTPUT on PIN 4
sheet 9
- Make sure this line does not hold LMK high
  before LMK can be programmed for SDO
sheet 10
- 12500 TI Boulevard. Dallas, Texas 75243
